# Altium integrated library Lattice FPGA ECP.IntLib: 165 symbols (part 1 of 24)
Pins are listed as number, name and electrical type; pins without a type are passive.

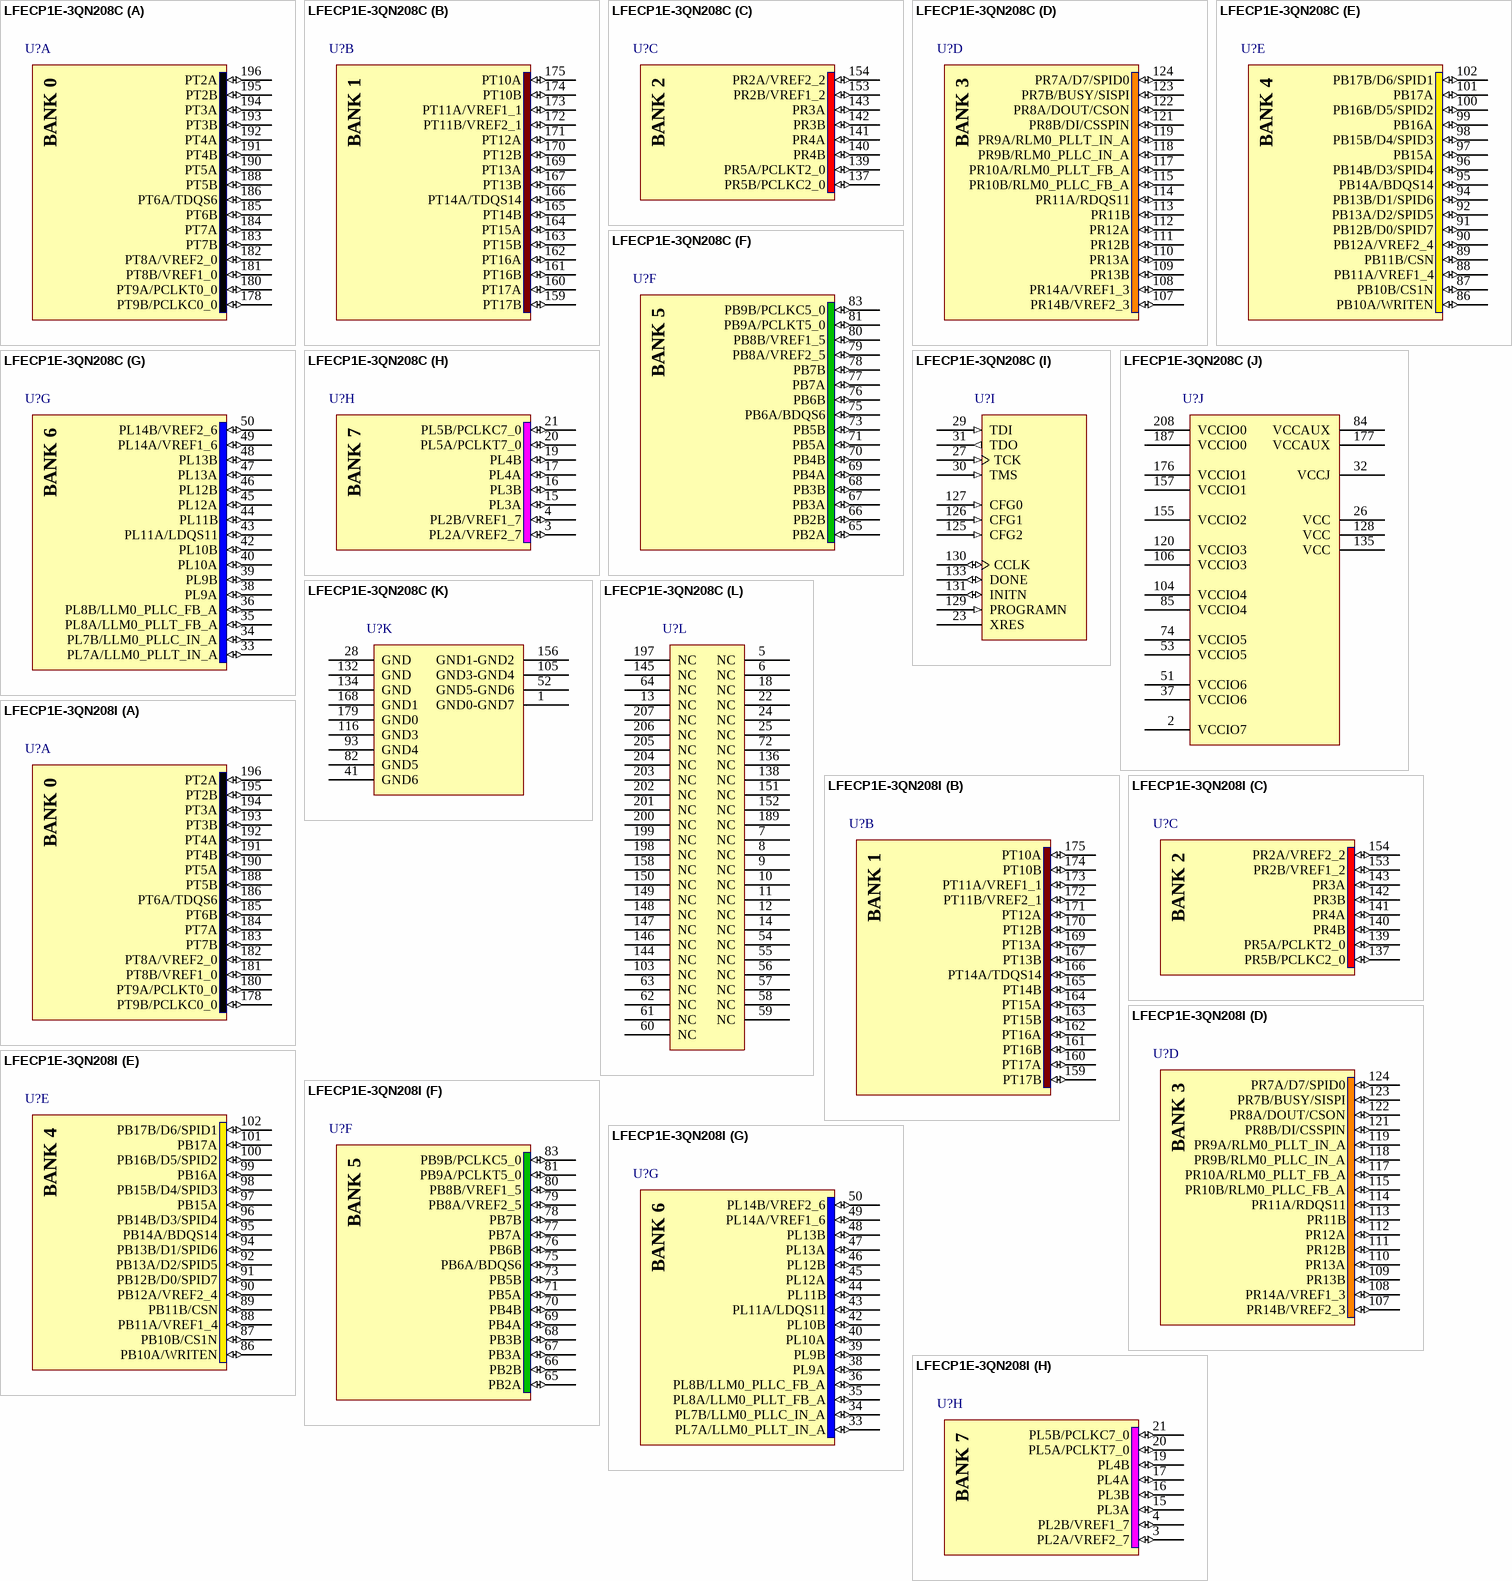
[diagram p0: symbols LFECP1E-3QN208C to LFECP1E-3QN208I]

## LFECP1E-3QN208C
designator U?
ECP 1.2V FPGA, 112 I/Os, 2 PLLs, 1.5K LUTs, 208-Pin PQFP, Pb-Free, Speed Grade 3, Commercial Temperature Grade; Note: Pins 1, 52, 105 and 156 are double bonded.; ComponentAvailability: Not Available
footprint PQFP208_N (Shrink QFP, 208-Leads, Body 28x28mm, Pitch 0.5mm, IPC Medium Density)
footprint PQFP208_L (Shrink QFP, 208-Leads, Body 28x28mm, Pitch 0.5mm, IPC High Density)
footprint PQFP208_M (Shrink QFP, 208-Leads, Body 28x28mm, Pitch 0.5mm, IPC Low Density)
3D model ECP1E-PQFP-208 (208-Pin Plastic Quad Flat Pack (PQFP208))
part A pins: 178 PT9B/PCLKC0_0 (io), 180 PT9A/PCLKT0_0 (io), 181 PT8B/VREF1_0 (io), 182 PT8A/VREF2_0 (io), 183 PT7B (io), 184 PT7A (io), 185 PT6B (io), 186 PT6A/TDQS6 (io), 188 PT5B (io), 190 PT5A (io), 191 PT4B (io), 192 PT4A (io), 193 PT3B (io), 194 PT3A (io), 195 PT2B (io), 196 PT2A (io)
part B pins: 159 PT17B (io), 160 PT17A (io), 161 PT16B (io), 162 PT16A (io), 163 PT15B (io), 164 PT15A (io), 165 PT14B (io), 166 PT14A/TDQS14 (io), 167 PT13B (io), 169 PT13A (io), 170 PT12B (io), 171 PT12A (io), 172 PT11B/VREF2_1 (io), 173 PT11A/VREF1_1 (io), 174 PT10B (io), 175 PT10A (io)
part C pins: 137 PR5B/PCLKC2_0 (io), 139 PR5A/PCLKT2_0 (io), 140 PR4B (io), 141 PR4A (io), 142 PR3B (io), 143 PR3A (io), 153 PR2B/VREF1_2 (io), 154 PR2A/VREF2_2 (io)
part D pins: 107 PR14B/VREF2_3 (io), 108 PR14A/VREF1_3 (io), 109 PR13B (io), 110 PR13A (io), 111 PR12B (io), 112 PR12A (io), 113 PR11B (io), 114 PR11A/RDQS11 (io), 115 PR10B/RLM0_PLLC_FB_A (io), 117 PR10A/RLM0_PLLT_FB_A (io), 118 PR9B/RLM0_PLLC_IN_A (io), 119 PR9A/RLM0_PLLT_IN_A (io), 121 PR8B/DI/CSSPIN (io), 122 PR8A/DOUT/CSON (io), 123 PR7B/BUSY/SISPI (io), 124 PR7A/D7/SPID0 (io)
part E pins: 86 PB10A/WRITEN (io), 87 PB10B/CS1N (io), 88 PB11A/VREF1_4 (io), 89 PB11B/CSN (io), 90 PB12A/VREF2_4 (io), 91 PB12B/D0/SPID7 (io), 92 PB13A/D2/SPID5 (io), 94 PB13B/D1/SPID6 (io), 95 PB14A/BDQS14 (io), 96 PB14B/D3/SPID4 (io), 97 PB15A (io), 98 PB15B/D4/SPID3 (io), 99 PB16A (io), 100 PB16B/D5/SPID2 (io), 101 PB17A (io), 102 PB17B/D6/SPID1 (io)
part F pins: 65 PB2A (io), 66 PB2B (io), 67 PB3A (io), 68 PB3B (io), 69 PB4A (io), 70 PB4B (io), 71 PB5A (io), 73 PB5B (io), 75 PB6A/BDQS6 (io), 76 PB6B (io), 77 PB7A (io), 78 PB7B (io), 79 PB8A/VREF2_5 (io), 80 PB8B/VREF1_5 (io), 81 PB9A/PCLKT5_0 (io), 83 PB9B/PCLKC5_0 (io)
part G pins: 33 PL7A/LLM0_PLLT_IN_A (io), 34 PL7B/LLM0_PLLC_IN_A (io), 35 PL8A/LLM0_PLLT_FB_A (io), 36 PL8B/LLM0_PLLC_FB_A (io), 38 PL9A (io), 39 PL9B (io), 40 PL10A (io), 42 PL10B (io), 43 PL11A/LDQS11 (io), 44 PL11B (io), 45 PL12A (io), 46 PL12B (io), 47 PL13A (io), 48 PL13B (io), 49 PL14A/VREF1_6 (io), 50 PL14B/VREF2_6 (io)
part H pins: 3 PL2A/VREF2_7 (io), 4 PL2B/VREF1_7 (io), 15 PL3A (io), 16 PL3B (io), 17 PL4A (io), 19 PL4B (io), 20 PL5A/PCLKT7_0 (io), 21 PL5B/PCLKC7_0 (io)
part I pins: 23 XRES, 27 TCK (in), 29 TDI (in), 30 TMS (in), 31 TDO (out), 125 CFG2 (in), 126 CFG1 (in), 127 CFG0 (in), 129 PROGRAMN (in), 130 CCLK (io), 131 INITN (io), 133 DONE (io)
part J pins: 2 VCCIO7 (power), 26 VCC (power), 32 VCCJ (power), 37 VCCIO6 (power), 51 VCCIO6 (power), 53 VCCIO5 (power), 74 VCCIO5 (power), 84 VCCAUX (power), 85 VCCIO4 (power), 104 VCCIO4 (power), 106 VCCIO3 (power), 120 VCCIO3 (power), 128 VCC (power), 135 VCC (power), 155 VCCIO2 (power), 157 VCCIO1 (power), 176 VCCIO1 (power), 177 VCCAUX (power), 187 VCCIO0 (power), 208 VCCIO0 (power)
part K pins: 1 GND0-GND7 (power), 28 GND (power), 41 GND6 (power), 52 GND5-GND6 (power), 82 GND5 (power), 93 GND4 (power), 105 GND3-GND4 (power), 116 GND3 (power), 132 GND (power), 134 GND (power), 156 GND1-GND2 (power), 168 GND1 (power), 179 GND0 (power)
part L pins: 5 NC, 6 NC, 7 NC, 8 NC, 9 NC, 10 NC, 11 NC, 12 NC, 13 NC, 14 NC, 18 NC, 22 NC, 24 NC, 25 NC, 54 NC, 55 NC, 56 NC, 57 NC, 58 NC, 59 NC, 60 NC, 61 NC, 62 NC, 63 NC, 64 NC, 72 NC, 103 NC, 136 NC, 138 NC, 144 NC, 145 NC, 146 NC, 147 NC, 148 NC, 149 NC, 150 NC, 151 NC, 152 NC, 158 NC, 189 NC, 197 NC, 198 NC, 199 NC, 200 NC, 201 NC, 202 NC, 203 NC, 204 NC, 205 NC, 206 NC, 207 NC

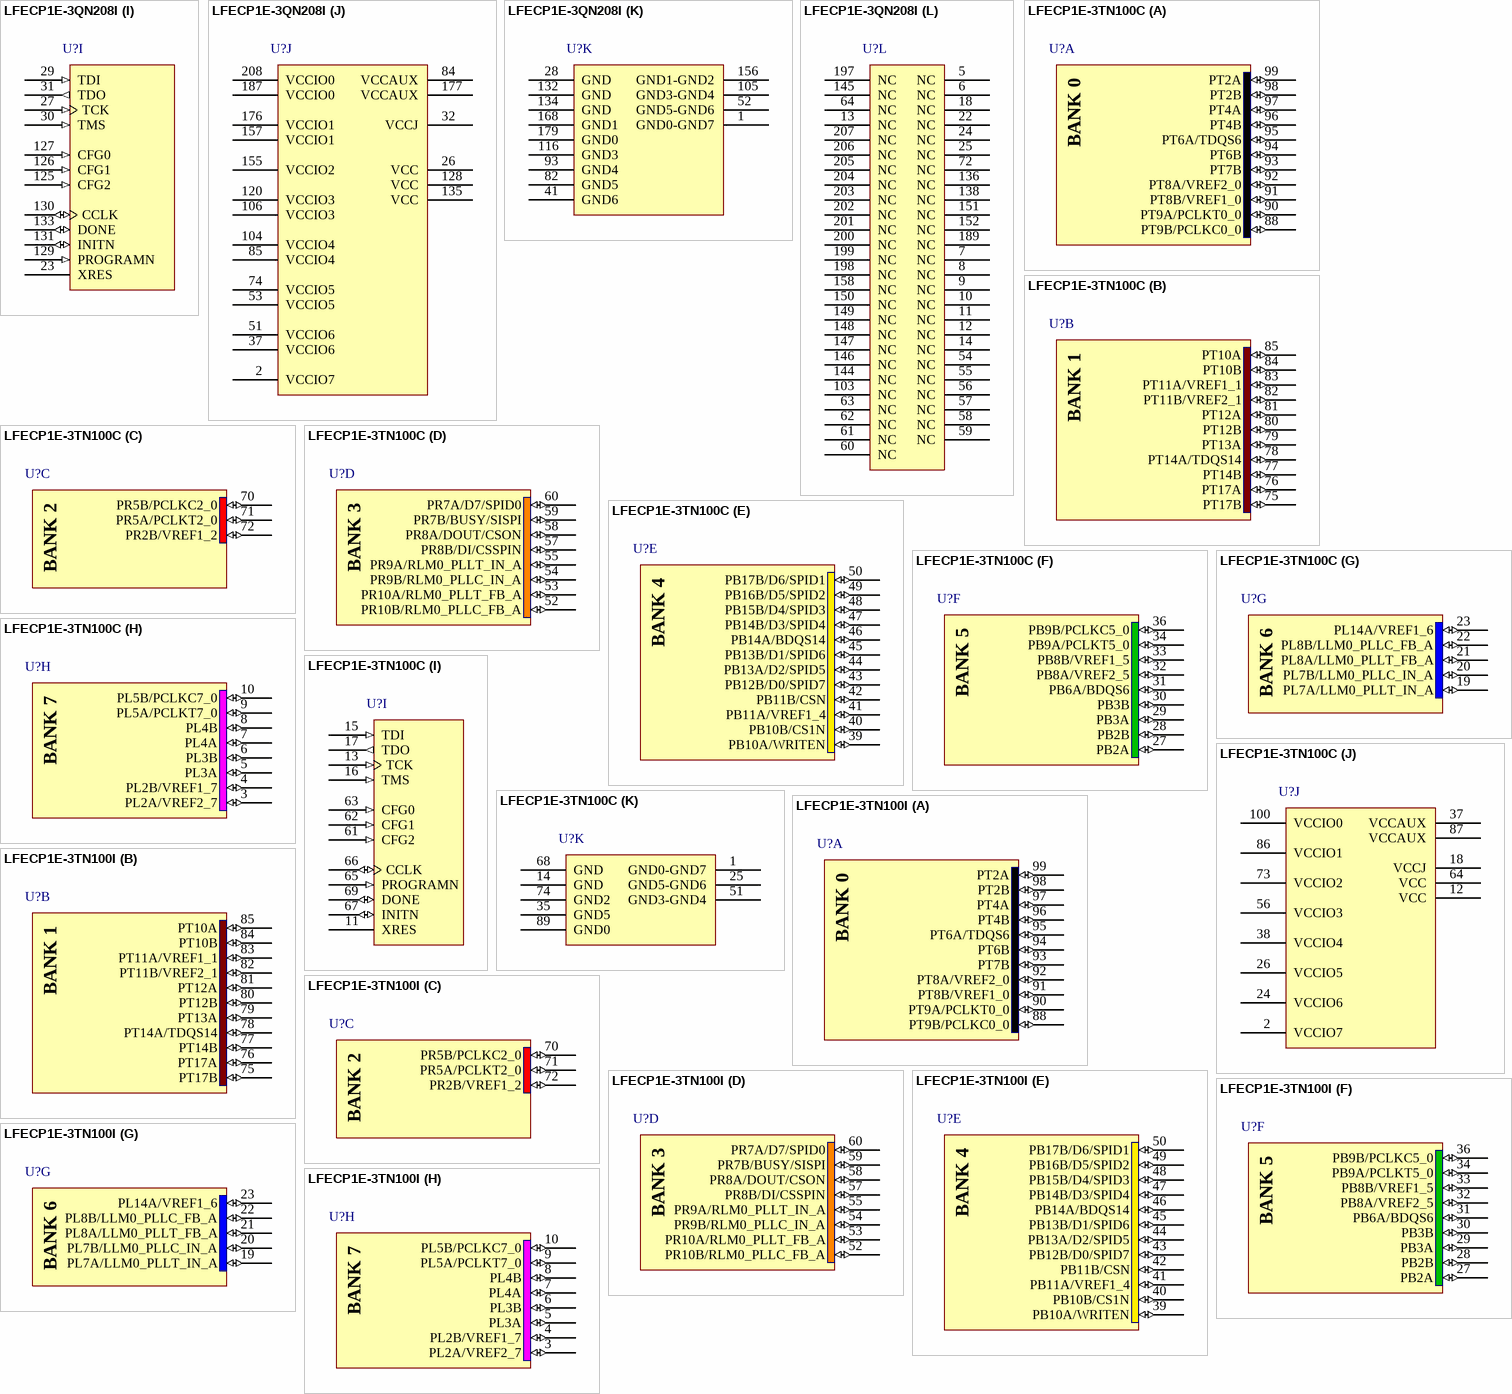
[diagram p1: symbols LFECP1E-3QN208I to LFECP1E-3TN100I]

## LFECP1E-3QN208I
designator U?
ECP 1.2V FPGA, 112 I/Os, 2 PLLs, 1.5K LUTs, 208-Pin PQFP, Pb-Free, Speed Grade 3, Industrial Temperature Grade; Note: Pins 1, 52, 105 and 156 are double bonded.; ComponentAvailability: Not Available
footprint PQFP208_N (Shrink QFP, 208-Leads, Body 28x28mm, Pitch 0.5mm, IPC Medium Density)
footprint PQFP208_L (Shrink QFP, 208-Leads, Body 28x28mm, Pitch 0.5mm, IPC High Density)
footprint PQFP208_M (Shrink QFP, 208-Leads, Body 28x28mm, Pitch 0.5mm, IPC Low Density)
3D model ECP1E-PQFP-208 (208-Pin Plastic Quad Flat Pack (PQFP208))
part A pins: 178 PT9B/PCLKC0_0 (io), 180 PT9A/PCLKT0_0 (io), 181 PT8B/VREF1_0 (io), 182 PT8A/VREF2_0 (io), 183 PT7B (io), 184 PT7A (io), 185 PT6B (io), 186 PT6A/TDQS6 (io), 188 PT5B (io), 190 PT5A (io), 191 PT4B (io), 192 PT4A (io), 193 PT3B (io), 194 PT3A (io), 195 PT2B (io), 196 PT2A (io)
part B pins: 159 PT17B (io), 160 PT17A (io), 161 PT16B (io), 162 PT16A (io), 163 PT15B (io), 164 PT15A (io), 165 PT14B (io), 166 PT14A/TDQS14 (io), 167 PT13B (io), 169 PT13A (io), 170 PT12B (io), 171 PT12A (io), 172 PT11B/VREF2_1 (io), 173 PT11A/VREF1_1 (io), 174 PT10B (io), 175 PT10A (io)
part C pins: 137 PR5B/PCLKC2_0 (io), 139 PR5A/PCLKT2_0 (io), 140 PR4B (io), 141 PR4A (io), 142 PR3B (io), 143 PR3A (io), 153 PR2B/VREF1_2 (io), 154 PR2A/VREF2_2 (io)
part D pins: 107 PR14B/VREF2_3 (io), 108 PR14A/VREF1_3 (io), 109 PR13B (io), 110 PR13A (io), 111 PR12B (io), 112 PR12A (io), 113 PR11B (io), 114 PR11A/RDQS11 (io), 115 PR10B/RLM0_PLLC_FB_A (io), 117 PR10A/RLM0_PLLT_FB_A (io), 118 PR9B/RLM0_PLLC_IN_A (io), 119 PR9A/RLM0_PLLT_IN_A (io), 121 PR8B/DI/CSSPIN (io), 122 PR8A/DOUT/CSON (io), 123 PR7B/BUSY/SISPI (io), 124 PR7A/D7/SPID0 (io)
part E pins: 86 PB10A/WRITEN (io), 87 PB10B/CS1N (io), 88 PB11A/VREF1_4 (io), 89 PB11B/CSN (io), 90 PB12A/VREF2_4 (io), 91 PB12B/D0/SPID7 (io), 92 PB13A/D2/SPID5 (io), 94 PB13B/D1/SPID6 (io), 95 PB14A/BDQS14 (io), 96 PB14B/D3/SPID4 (io), 97 PB15A (io), 98 PB15B/D4/SPID3 (io), 99 PB16A (io), 100 PB16B/D5/SPID2 (io), 101 PB17A (io), 102 PB17B/D6/SPID1 (io)
part F pins: 65 PB2A (io), 66 PB2B (io), 67 PB3A (io), 68 PB3B (io), 69 PB4A (io), 70 PB4B (io), 71 PB5A (io), 73 PB5B (io), 75 PB6A/BDQS6 (io), 76 PB6B (io), 77 PB7A (io), 78 PB7B (io), 79 PB8A/VREF2_5 (io), 80 PB8B/VREF1_5 (io), 81 PB9A/PCLKT5_0 (io), 83 PB9B/PCLKC5_0 (io)
part G pins: 33 PL7A/LLM0_PLLT_IN_A (io), 34 PL7B/LLM0_PLLC_IN_A (io), 35 PL8A/LLM0_PLLT_FB_A (io), 36 PL8B/LLM0_PLLC_FB_A (io), 38 PL9A (io), 39 PL9B (io), 40 PL10A (io), 42 PL10B (io), 43 PL11A/LDQS11 (io), 44 PL11B (io), 45 PL12A (io), 46 PL12B (io), 47 PL13A (io), 48 PL13B (io), 49 PL14A/VREF1_6 (io), 50 PL14B/VREF2_6 (io)
part H pins: 3 PL2A/VREF2_7 (io), 4 PL2B/VREF1_7 (io), 15 PL3A (io), 16 PL3B (io), 17 PL4A (io), 19 PL4B (io), 20 PL5A/PCLKT7_0 (io), 21 PL5B/PCLKC7_0 (io)
part I pins: 23 XRES, 27 TCK (in), 29 TDI (in), 30 TMS (in), 31 TDO (out), 125 CFG2 (in), 126 CFG1 (in), 127 CFG0 (in), 129 PROGRAMN (in), 130 CCLK (io), 131 INITN (io), 133 DONE (io)
part J pins: 2 VCCIO7 (power), 26 VCC (power), 32 VCCJ (power), 37 VCCIO6 (power), 51 VCCIO6 (power), 53 VCCIO5 (power), 74 VCCIO5 (power), 84 VCCAUX (power), 85 VCCIO4 (power), 104 VCCIO4 (power), 106 VCCIO3 (power), 120 VCCIO3 (power), 128 VCC (power), 135 VCC (power), 155 VCCIO2 (power), 157 VCCIO1 (power), 176 VCCIO1 (power), 177 VCCAUX (power), 187 VCCIO0 (power), 208 VCCIO0 (power)
part K pins: 1 GND0-GND7 (power), 28 GND (power), 41 GND6 (power), 52 GND5-GND6 (power), 82 GND5 (power), 93 GND4 (power), 105 GND3-GND4 (power), 116 GND3 (power), 132 GND (power), 134 GND (power), 156 GND1-GND2 (power), 168 GND1 (power), 179 GND0 (power)
part L pins: 5 NC, 6 NC, 7 NC, 8 NC, 9 NC, 10 NC, 11 NC, 12 NC, 13 NC, 14 NC, 18 NC, 22 NC, 24 NC, 25 NC, 54 NC, 55 NC, 56 NC, 57 NC, 58 NC, 59 NC, 60 NC, 61 NC, 62 NC, 63 NC, 64 NC, 72 NC, 103 NC, 136 NC, 138 NC, 144 NC, 145 NC, 146 NC, 147 NC, 148 NC, 149 NC, 150 NC, 151 NC, 152 NC, 158 NC, 189 NC, 197 NC, 198 NC, 199 NC, 200 NC, 201 NC, 202 NC, 203 NC, 204 NC, 205 NC, 206 NC, 207 NC

## LFECP1E-3TN100C
designator U?
ECP 1.2V FPGA, 67 I/Os, 2 PLLs, 1.5K LUTs, 100-Pin TQFP, Pb-Free, Speed Grade 3, Commercial Temperature Grade; Note: Pins 1, 25 and 51 are double bonded.; ComponentAvailability: Not Available
footprint TQFP100_N (Thin QFP, 100-Leads, Body 14x14mm, Pitch 0.5mm, IPC Medium Density)
footprint TQFP100_L (Thin QFP, 100-Leads, Body 14x14mm, Pitch 0.5mm, IPC High Density)
footprint TQFP100_M (Thin QFP, 100-Leads, Body 14x14mm, Pitch 0.5mm, IPC Low Density)
3D model ECP1E-TQFP-100 (100-Pin Thin Quad Flat Pack (TQFP100))
part A pins: 88 PT9B/PCLKC0_0 (io), 90 PT9A/PCLKT0_0 (io), 91 PT8B/VREF1_0 (io), 92 PT8A/VREF2_0 (io), 93 PT7B (io), 94 PT6B (io), 95 PT6A/TDQS6 (io), 96 PT4B (io), 97 PT4A (io), 98 PT2B (io), 99 PT2A (io)
part B pins: 75 PT17B (io), 76 PT17A (io), 77 PT14B (io), 78 PT14A/TDQS14 (io), 79 PT13A (io), 80 PT12B (io), 81 PT12A (io), 82 PT11B/VREF2_1 (io), 83 PT11A/VREF1_1 (io), 84 PT10B (io), 85 PT10A (io)
part C pins: 70 PR5B/PCLKC2_0 (io), 71 PR5A/PCLKT2_0 (io), 72 PR2B/VREF1_2 (io)
part D pins: 52 PR10B/RLM0_PLLC_FB_A (io), 53 PR10A/RLM0_PLLT_FB_A (io), 54 PR9B/RLM0_PLLC_IN_A (io), 55 PR9A/RLM0_PLLT_IN_A (io), 57 PR8B/DI/CSSPIN (io), 58 PR8A/DOUT/CSON (io), 59 PR7B/BUSY/SISPI (io), 60 PR7A/D7/SPID0 (io)
part E pins: 39 PB10A/WRITEN (io), 40 PB10B/CS1N (io), 41 PB11A/VREF1_4 (io), 42 PB11B/CSN (io), 43 PB12B/D0/SPID7 (io), 44 PB13A/D2/SPID5 (io), 45 PB13B/D1/SPID6 (io), 46 PB14A/BDQS14 (io), 47 PB14B/D3/SPID4 (io), 48 PB15B/D4/SPID3 (io), 49 PB16B/D5/SPID2 (io), 50 PB17B/D6/SPID1 (io)
part F pins: 27 PB2A (io), 28 PB2B (io), 29 PB3A (io), 30 PB3B (io), 31 PB6A/BDQS6 (io), 32 PB8A/VREF2_5 (io), 33 PB8B/VREF1_5 (io), 34 PB9A/PCLKT5_0 (io), 36 PB9B/PCLKC5_0 (io)
part G pins: 19 PL7A/LLM0_PLLT_IN_A (io), 20 PL7B/LLM0_PLLC_IN_A (io), 21 PL8A/LLM0_PLLT_FB_A (io), 22 PL8B/LLM0_PLLC_FB_A (io), 23 PL14A/VREF1_6 (io)
part H pins: 3 PL2A/VREF2_7 (io), 4 PL2B/VREF1_7 (io), 5 PL3A (io), 6 PL3B (io), 7 PL4A (io), 8 PL4B (io), 9 PL5A/PCLKT7_0 (io), 10 PL5B/PCLKC7_0 (io)
part I pins: 11 XRES, 13 TCK (in), 15 TDI (in), 16 TMS (in), 17 TDO (out), 61 CFG2 (in), 62 CFG1 (in), 63 CFG0 (in), 65 PROGRAMN (in), 66 CCLK (io), 67 INITN (io), 69 DONE (io)
part J pins: 2 VCCIO7 (power), 12 VCC (power), 18 VCCJ (power), 24 VCCIO6 (power), 26 VCCIO5 (power), 37 VCCAUX (power), 38 VCCIO4 (power), 56 VCCIO3 (power), 64 VCC (power), 73 VCCIO2 (power), 86 VCCIO1 (power), 87 VCCAUX (power), 100 VCCIO0 (power)
part K pins: 1 GND0-GND7 (power), 14 GND (power), 25 GND5-GND6 (power), 35 GND5 (power), 51 GND3-GND4 (power), 68 GND (power), 74 GND2 (power), 89 GND0 (power)

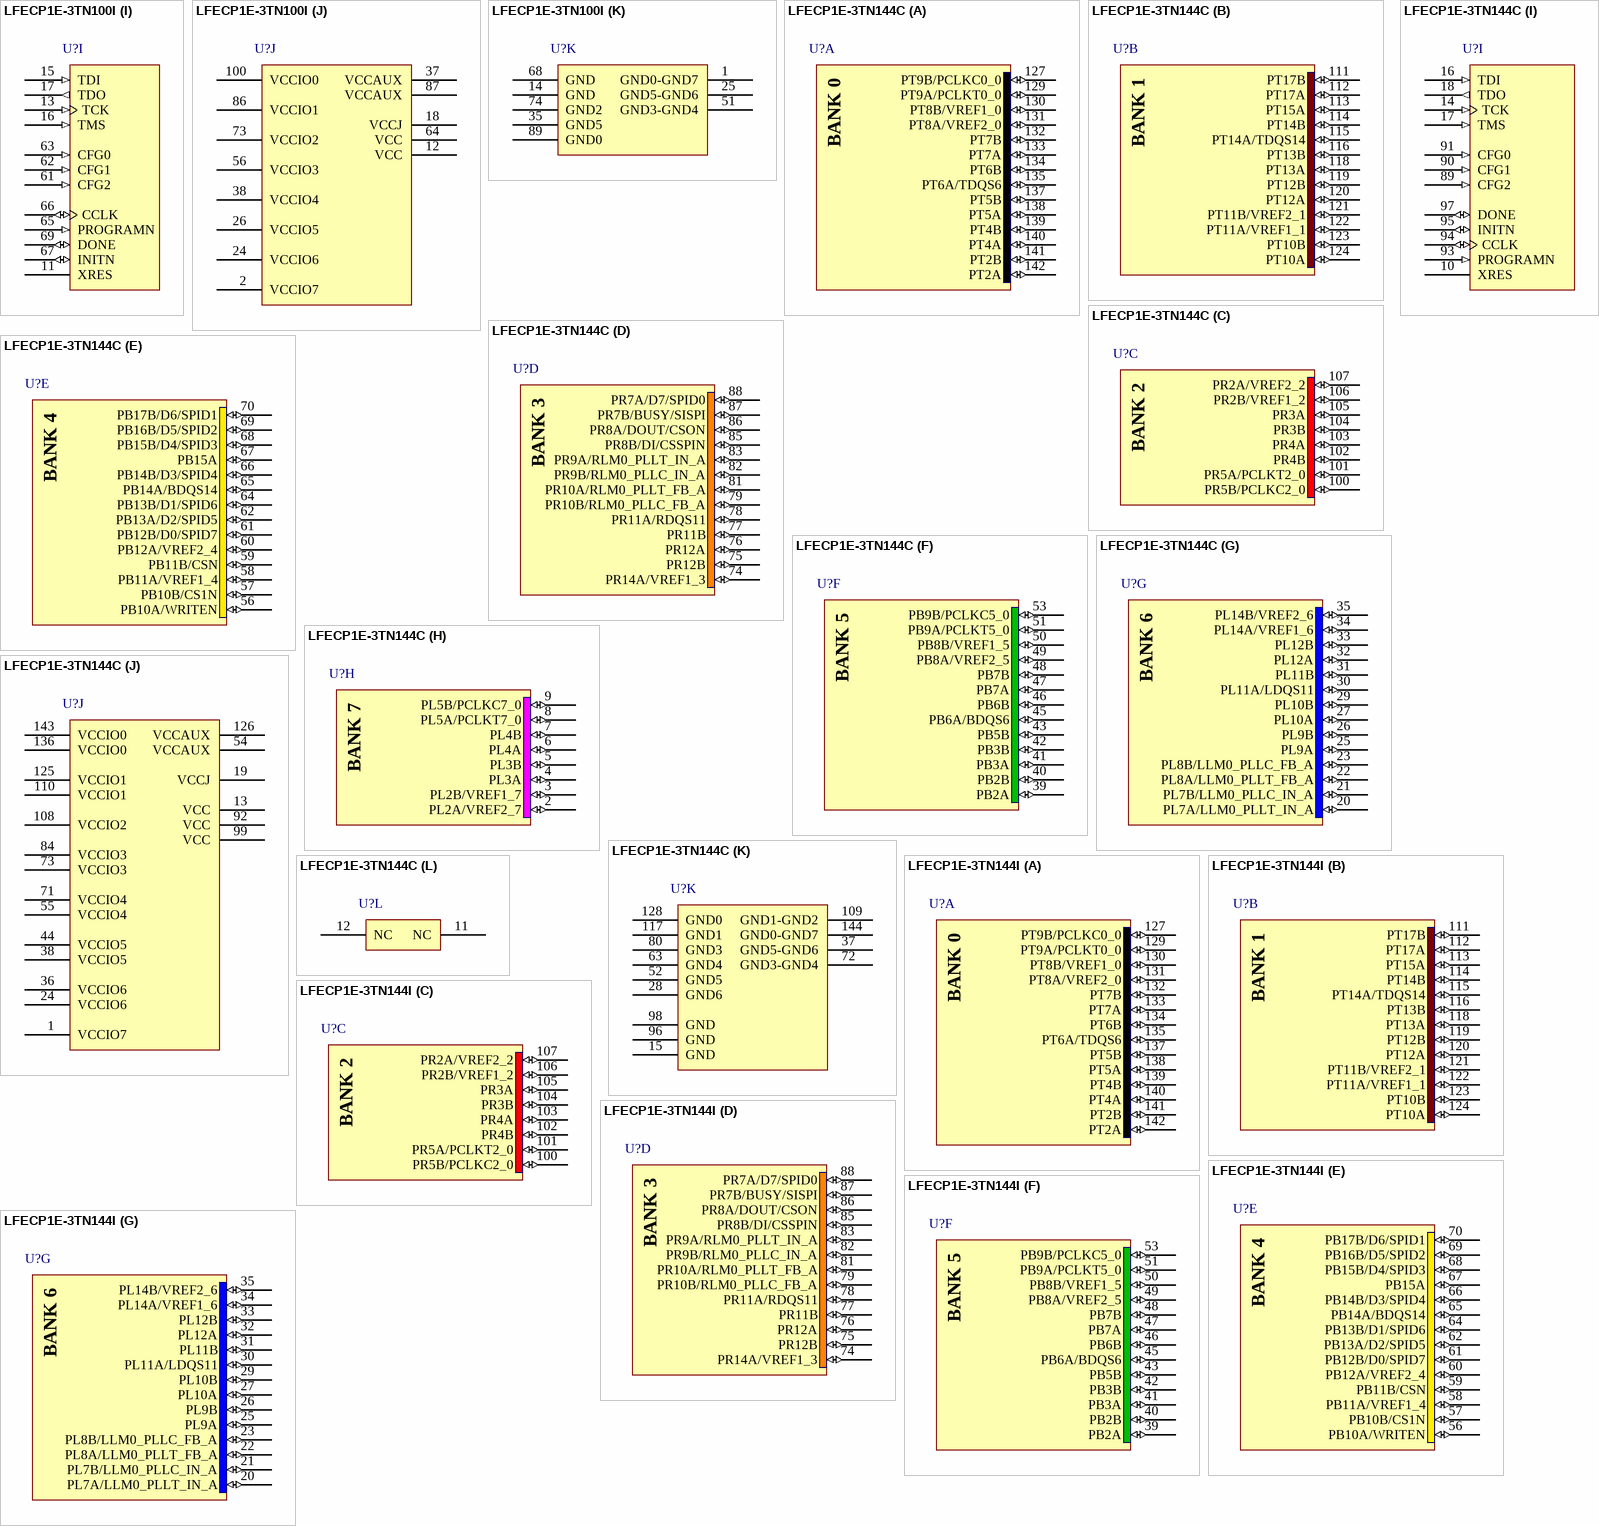
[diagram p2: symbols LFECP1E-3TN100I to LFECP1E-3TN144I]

## LFECP1E-3TN100I
designator U?
ECP 1.2V FPGA, 67 I/Os, 2 PLLs, 1.5K LUTs, 100-Pin TQFP, Pb-Free, Speed Grade 3, Industrial Temperature Grade; Note: Pins 1, 25 and 51 are double bonded.; ComponentAvailability: Not Available
footprint TQFP100_N (Thin QFP, 100-Leads, Body 14x14mm, Pitch 0.5mm, IPC Medium Density)
footprint TQFP100_L (Thin QFP, 100-Leads, Body 14x14mm, Pitch 0.5mm, IPC High Density)
footprint TQFP100_M (Thin QFP, 100-Leads, Body 14x14mm, Pitch 0.5mm, IPC Low Density)
3D model ECP1E-TQFP-100 (100-Pin Thin Quad Flat Pack (TQFP100))
part A pins: 88 PT9B/PCLKC0_0 (io), 90 PT9A/PCLKT0_0 (io), 91 PT8B/VREF1_0 (io), 92 PT8A/VREF2_0 (io), 93 PT7B (io), 94 PT6B (io), 95 PT6A/TDQS6 (io), 96 PT4B (io), 97 PT4A (io), 98 PT2B (io), 99 PT2A (io)
part B pins: 75 PT17B (io), 76 PT17A (io), 77 PT14B (io), 78 PT14A/TDQS14 (io), 79 PT13A (io), 80 PT12B (io), 81 PT12A (io), 82 PT11B/VREF2_1 (io), 83 PT11A/VREF1_1 (io), 84 PT10B (io), 85 PT10A (io)
part C pins: 70 PR5B/PCLKC2_0 (io), 71 PR5A/PCLKT2_0 (io), 72 PR2B/VREF1_2 (io)
part D pins: 52 PR10B/RLM0_PLLC_FB_A (io), 53 PR10A/RLM0_PLLT_FB_A (io), 54 PR9B/RLM0_PLLC_IN_A (io), 55 PR9A/RLM0_PLLT_IN_A (io), 57 PR8B/DI/CSSPIN (io), 58 PR8A/DOUT/CSON (io), 59 PR7B/BUSY/SISPI (io), 60 PR7A/D7/SPID0 (io)
part E pins: 39 PB10A/WRITEN (io), 40 PB10B/CS1N (io), 41 PB11A/VREF1_4 (io), 42 PB11B/CSN (io), 43 PB12B/D0/SPID7 (io), 44 PB13A/D2/SPID5 (io), 45 PB13B/D1/SPID6 (io), 46 PB14A/BDQS14 (io), 47 PB14B/D3/SPID4 (io), 48 PB15B/D4/SPID3 (io), 49 PB16B/D5/SPID2 (io), 50 PB17B/D6/SPID1 (io)
part F pins: 27 PB2A (io), 28 PB2B (io), 29 PB3A (io), 30 PB3B (io), 31 PB6A/BDQS6 (io), 32 PB8A/VREF2_5 (io), 33 PB8B/VREF1_5 (io), 34 PB9A/PCLKT5_0 (io), 36 PB9B/PCLKC5_0 (io)
part G pins: 19 PL7A/LLM0_PLLT_IN_A (io), 20 PL7B/LLM0_PLLC_IN_A (io), 21 PL8A/LLM0_PLLT_FB_A (io), 22 PL8B/LLM0_PLLC_FB_A (io), 23 PL14A/VREF1_6 (io)
part H pins: 3 PL2A/VREF2_7 (io), 4 PL2B/VREF1_7 (io), 5 PL3A (io), 6 PL3B (io), 7 PL4A (io), 8 PL4B (io), 9 PL5A/PCLKT7_0 (io), 10 PL5B/PCLKC7_0 (io)
part I pins: 11 XRES, 13 TCK (in), 15 TDI (in), 16 TMS (in), 17 TDO (out), 61 CFG2 (in), 62 CFG1 (in), 63 CFG0 (in), 65 PROGRAMN (in), 66 CCLK (io), 67 INITN (io), 69 DONE (io)
part J pins: 2 VCCIO7 (power), 12 VCC (power), 18 VCCJ (power), 24 VCCIO6 (power), 26 VCCIO5 (power), 37 VCCAUX (power), 38 VCCIO4 (power), 56 VCCIO3 (power), 64 VCC (power), 73 VCCIO2 (power), 86 VCCIO1 (power), 87 VCCAUX (power), 100 VCCIO0 (power)
part K pins: 1 GND0-GND7 (power), 14 GND (power), 25 GND5-GND6 (power), 35 GND5 (power), 51 GND3-GND4 (power), 68 GND (power), 74 GND2 (power), 89 GND0 (power)

## LFECP1E-3TN144C
designator U?
ECP 1.2V FPGA, 97 I/Os, 2 PLLs, 1.5K LUTs, 144-Pin TQFP, Pb-Free, Speed Grade 3, Commercial Temperature Grade; Note: Pins 37, 72, 109 and 144 are double bonded.; ComponentAvailability: Not Available
footprint TQFP144_N (Thin QFP, 144-Leads, Body 20x20mm, Pitch 0.5mm, IPC Medium Density)
footprint TQFP144_L (Thin QFP, 144-Leads, Body 20x20mm, Pitch 0.5mm, IPC High Density)
footprint TQFP144_M (Thin QFP, 144-Leads, Body 20x20mm, Pitch 0.5mm, IPC Low Density)
3D model ECP1E-TQFP-144 (144-Pin Thin Quad Flat Pack (TQFP144))
part A pins: 127 PT9B/PCLKC0_0 (io), 129 PT9A/PCLKT0_0 (io), 130 PT8B/VREF1_0 (io), 131 PT8A/VREF2_0 (io), 132 PT7B (io), 133 PT7A (io), 134 PT6B (io), 135 PT6A/TDQS6 (io), 137 PT5B (io), 138 PT5A (io), 139 PT4B (io), 140 PT4A (io), 141 PT2B (io), 142 PT2A (io)
part B pins: 111 PT17B (io), 112 PT17A (io), 113 PT15A (io), 114 PT14B (io), 115 PT14A/TDQS14 (io), 116 PT13B (io), 118 PT13A (io), 119 PT12B (io), 120 PT12A (io), 121 PT11B/VREF2_1 (io), 122 PT11A/VREF1_1 (io), 123 PT10B (io), 124 PT10A (io)
part C pins: 100 PR5B/PCLKC2_0 (io), 101 PR5A/PCLKT2_0 (io), 102 PR4B (io), 103 PR4A (io), 104 PR3B (io), 105 PR3A (io), 106 PR2B/VREF1_2 (io), 107 PR2A/VREF2_2 (io)
part D pins: 74 PR14A/VREF1_3 (io), 75 PR12B (io), 76 PR12A (io), 77 PR11B (io), 78 PR11A/RDQS11 (io), 79 PR10B/RLM0_PLLC_FB_A (io), 81 PR10A/RLM0_PLLT_FB_A (io), 82 PR9B/RLM0_PLLC_IN_A (io), 83 PR9A/RLM0_PLLT_IN_A (io), 85 PR8B/DI/CSSPIN (io), 86 PR8A/DOUT/CSON (io), 87 PR7B/BUSY/SISPI (io), 88 PR7A/D7/SPID0 (io)
part E pins: 56 PB10A/WRITEN (io), 57 PB10B/CS1N (io), 58 PB11A/VREF1_4 (io), 59 PB11B/CSN (io), 60 PB12A/VREF2_4 (io), 61 PB12B/D0/SPID7 (io), 62 PB13A/D2/SPID5 (io), 64 PB13B/D1/SPID6 (io), 65 PB14A/BDQS14 (io), 66 PB14B/D3/SPID4 (io), 67 PB15A (io), 68 PB15B/D4/SPID3 (io), 69 PB16B/D5/SPID2 (io), 70 PB17B/D6/SPID1 (io)
part F pins: 39 PB2A (io), 40 PB2B (io), 41 PB3A (io), 42 PB3B (io), 43 PB5B (io), 45 PB6A/BDQS6 (io), 46 PB6B (io), 47 PB7A (io), 48 PB7B (io), 49 PB8A/VREF2_5 (io), 50 PB8B/VREF1_5 (io), 51 PB9A/PCLKT5_0 (io), 53 PB9B/PCLKC5_0 (io)
part G pins: 20 PL7A/LLM0_PLLT_IN_A (io), 21 PL7B/LLM0_PLLC_IN_A (io), 22 PL8A/LLM0_PLLT_FB_A (io), 23 PL8B/LLM0_PLLC_FB_A (io), 25 PL9A (io), 26 PL9B (io), 27 PL10A (io), 29 PL10B (io), 30 PL11A/LDQS11 (io), 31 PL11B (io), 32 PL12A (io), 33 PL12B (io), 34 PL14A/VREF1_6 (io), 35 PL14B/VREF2_6 (io)
part H pins: 2 PL2A/VREF2_7 (io), 3 PL2B/VREF1_7 (io), 4 PL3A (io), 5 PL3B (io), 6 PL4A (io), 7 PL4B (io), 8 PL5A/PCLKT7_0 (io), 9 PL5B/PCLKC7_0 (io)
part I pins: 10 XRES, 14 TCK (in), 16 TDI (in), 17 TMS (in), 18 TDO (out), 89 CFG2 (in), 90 CFG1 (in), 91 CFG0 (in), 93 PROGRAMN (in), 94 CCLK (io), 95 INITN (io), 97 DONE (io)
part J pins: 1 VCCIO7 (power), 13 VCC (power), 19 VCCJ (power), 24 VCCIO6 (power), 36 VCCIO6 (power), 38 VCCIO5 (power), 44 VCCIO5 (power), 54 VCCAUX (power), 55 VCCIO4 (power), 71 VCCIO4 (power), 73 VCCIO3 (power), 84 VCCIO3 (power), 92 VCC (power), 99 VCC (power), 108 VCCIO2 (power), 110 VCCIO1 (power), 125 VCCIO1 (power), 126 VCCAUX (power), 136 VCCIO0 (power), 143 VCCIO0 (power)
part K pins: 15 GND (power), 28 GND6 (power), 37 GND5-GND6 (power), 52 GND5 (power), 63 GND4 (power), 72 GND3-GND4 (power), 80 GND3 (power), 96 GND (power), 98 GND (power), 109 GND1-GND2 (power), 117 GND1 (power), 128 GND0 (power), 144 GND0-GND7 (power)
part L pins: 11 NC, 12 NC

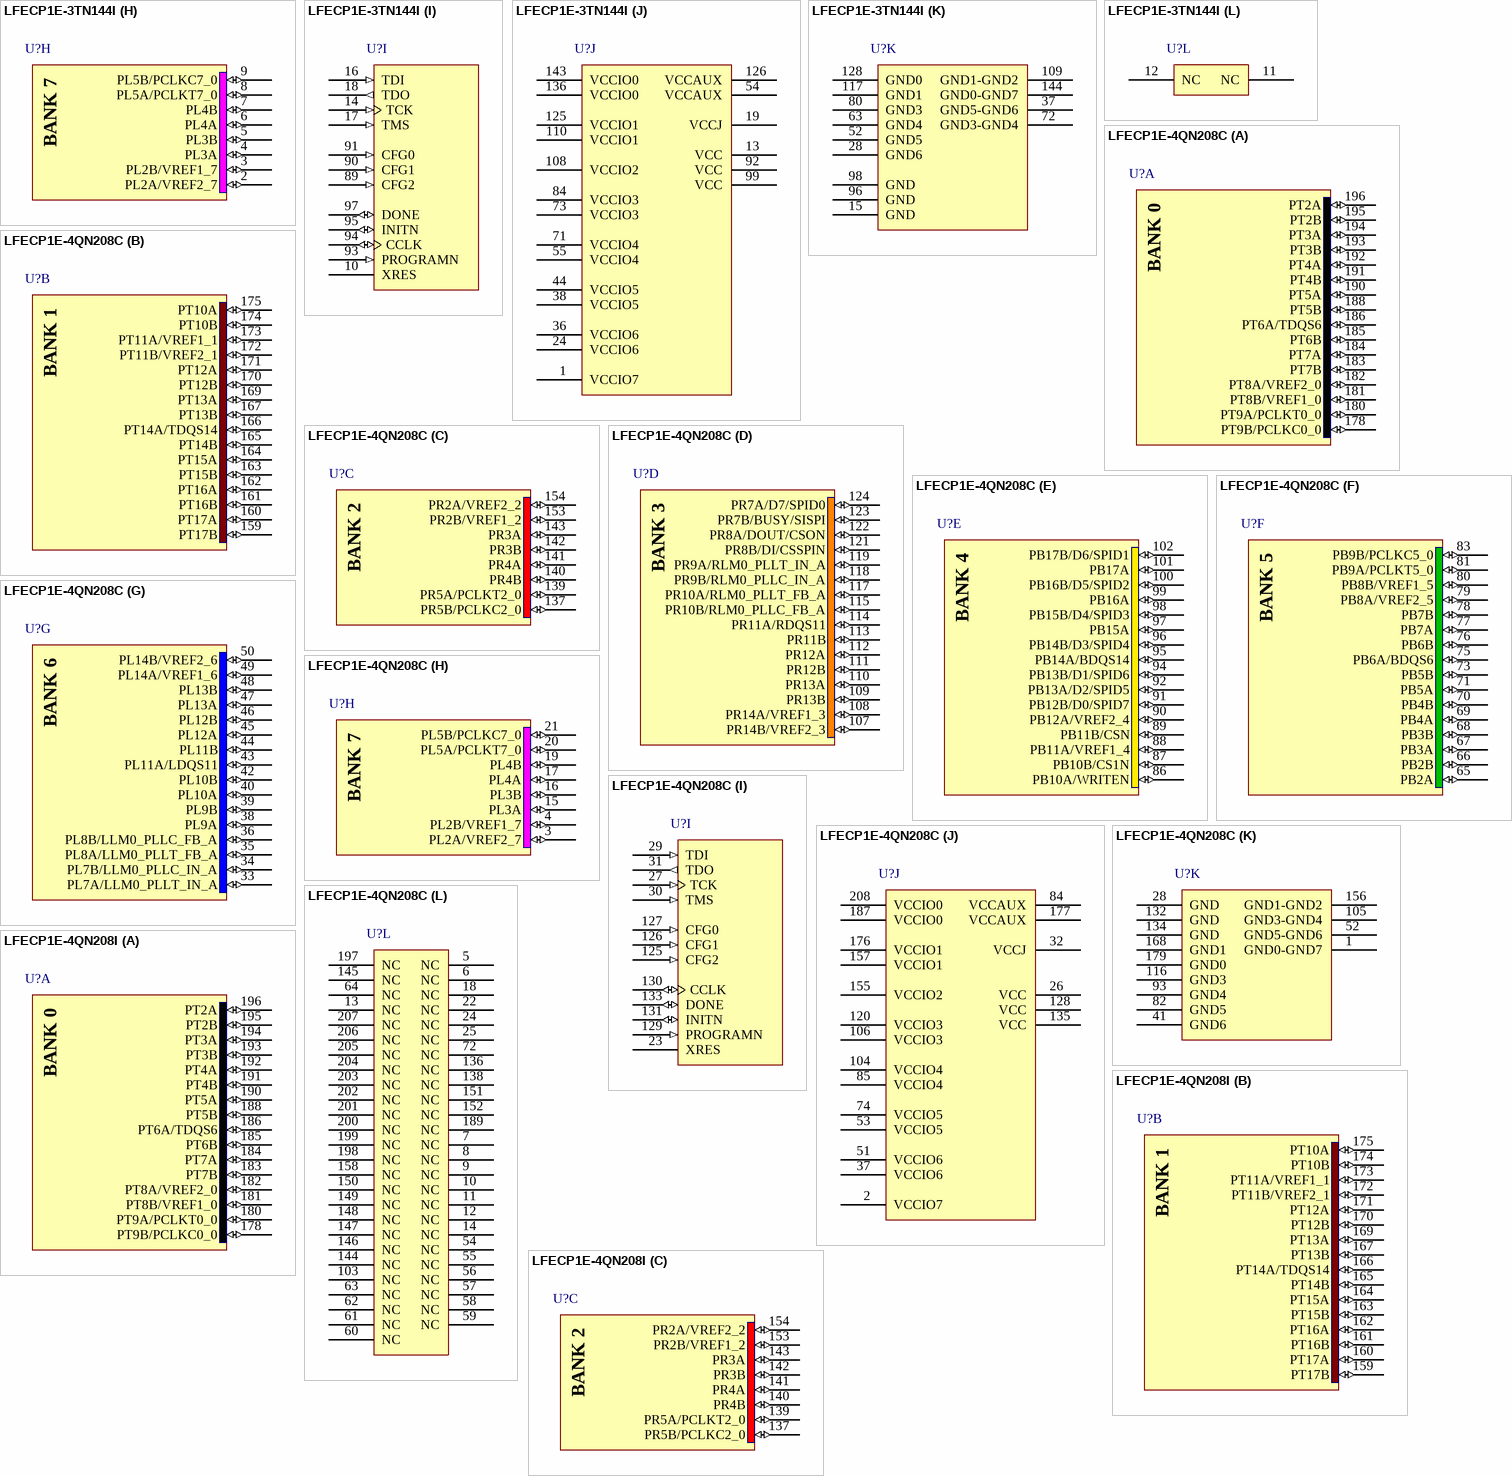
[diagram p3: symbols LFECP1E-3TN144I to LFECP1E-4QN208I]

## LFECP1E-3TN144I
designator U?
ECP 1.2V FPGA, 97 I/Os, 2 PLLs, 1.5K LUTs, 144-Pin TQFP, Pb-Free, Speed Grade 3, Industrial Temperature Grade; Note: Pins 37, 72, 109 and 144 are double bonded.; ComponentAvailability: Not Available
footprint TQFP144_N (Thin QFP, 144-Leads, Body 20x20mm, Pitch 0.5mm, IPC Medium Density)
footprint TQFP144_L (Thin QFP, 144-Leads, Body 20x20mm, Pitch 0.5mm, IPC High Density)
footprint TQFP144_M (Thin QFP, 144-Leads, Body 20x20mm, Pitch 0.5mm, IPC Low Density)
3D model ECP1E-TQFP-144 (144-Pin Thin Quad Flat Pack (TQFP144))
part A pins: 127 PT9B/PCLKC0_0 (io), 129 PT9A/PCLKT0_0 (io), 130 PT8B/VREF1_0 (io), 131 PT8A/VREF2_0 (io), 132 PT7B (io), 133 PT7A (io), 134 PT6B (io), 135 PT6A/TDQS6 (io), 137 PT5B (io), 138 PT5A (io), 139 PT4B (io), 140 PT4A (io), 141 PT2B (io), 142 PT2A (io)
part B pins: 111 PT17B (io), 112 PT17A (io), 113 PT15A (io), 114 PT14B (io), 115 PT14A/TDQS14 (io), 116 PT13B (io), 118 PT13A (io), 119 PT12B (io), 120 PT12A (io), 121 PT11B/VREF2_1 (io), 122 PT11A/VREF1_1 (io), 123 PT10B (io), 124 PT10A (io)
part C pins: 100 PR5B/PCLKC2_0 (io), 101 PR5A/PCLKT2_0 (io), 102 PR4B (io), 103 PR4A (io), 104 PR3B (io), 105 PR3A (io), 106 PR2B/VREF1_2 (io), 107 PR2A/VREF2_2 (io)
part D pins: 74 PR14A/VREF1_3 (io), 75 PR12B (io), 76 PR12A (io), 77 PR11B (io), 78 PR11A/RDQS11 (io), 79 PR10B/RLM0_PLLC_FB_A (io), 81 PR10A/RLM0_PLLT_FB_A (io), 82 PR9B/RLM0_PLLC_IN_A (io), 83 PR9A/RLM0_PLLT_IN_A (io), 85 PR8B/DI/CSSPIN (io), 86 PR8A/DOUT/CSON (io), 87 PR7B/BUSY/SISPI (io), 88 PR7A/D7/SPID0 (io)
part E pins: 56 PB10A/WRITEN (io), 57 PB10B/CS1N (io), 58 PB11A/VREF1_4 (io), 59 PB11B/CSN (io), 60 PB12A/VREF2_4 (io), 61 PB12B/D0/SPID7 (io), 62 PB13A/D2/SPID5 (io), 64 PB13B/D1/SPID6 (io), 65 PB14A/BDQS14 (io), 66 PB14B/D3/SPID4 (io), 67 PB15A (io), 68 PB15B/D4/SPID3 (io), 69 PB16B/D5/SPID2 (io), 70 PB17B/D6/SPID1 (io)
part F pins: 39 PB2A (io), 40 PB2B (io), 41 PB3A (io), 42 PB3B (io), 43 PB5B (io), 45 PB6A/BDQS6 (io), 46 PB6B (io), 47 PB7A (io), 48 PB7B (io), 49 PB8A/VREF2_5 (io), 50 PB8B/VREF1_5 (io), 51 PB9A/PCLKT5_0 (io), 53 PB9B/PCLKC5_0 (io)
part G pins: 20 PL7A/LLM0_PLLT_IN_A (io), 21 PL7B/LLM0_PLLC_IN_A (io), 22 PL8A/LLM0_PLLT_FB_A (io), 23 PL8B/LLM0_PLLC_FB_A (io), 25 PL9A (io), 26 PL9B (io), 27 PL10A (io), 29 PL10B (io), 30 PL11A/LDQS11 (io), 31 PL11B (io), 32 PL12A (io), 33 PL12B (io), 34 PL14A/VREF1_6 (io), 35 PL14B/VREF2_6 (io)
part H pins: 2 PL2A/VREF2_7 (io), 3 PL2B/VREF1_7 (io), 4 PL3A (io), 5 PL3B (io), 6 PL4A (io), 7 PL4B (io), 8 PL5A/PCLKT7_0 (io), 9 PL5B/PCLKC7_0 (io)
part I pins: 10 XRES, 14 TCK (in), 16 TDI (in), 17 TMS (in), 18 TDO (out), 89 CFG2 (in), 90 CFG1 (in), 91 CFG0 (in), 93 PROGRAMN (in), 94 CCLK (io), 95 INITN (io), 97 DONE (io)
part J pins: 1 VCCIO7 (power), 13 VCC (power), 19 VCCJ (power), 24 VCCIO6 (power), 36 VCCIO6 (power), 38 VCCIO5 (power), 44 VCCIO5 (power), 54 VCCAUX (power), 55 VCCIO4 (power), 71 VCCIO4 (power), 73 VCCIO3 (power), 84 VCCIO3 (power), 92 VCC (power), 99 VCC (power), 108 VCCIO2 (power), 110 VCCIO1 (power), 125 VCCIO1 (power), 126 VCCAUX (power), 136 VCCIO0 (power), 143 VCCIO0 (power)
part K pins: 15 GND (power), 28 GND6 (power), 37 GND5-GND6 (power), 52 GND5 (power), 63 GND4 (power), 72 GND3-GND4 (power), 80 GND3 (power), 96 GND (power), 98 GND (power), 109 GND1-GND2 (power), 117 GND1 (power), 128 GND0 (power), 144 GND0-GND7 (power)
part L pins: 11 NC, 12 NC

## LFECP1E-4QN208C
designator U?
ECP 1.2V FPGA, 112 I/Os, 2 PLLs, 1.5K LUTs, 208-Pin PQFP, Pb-Free, Speed Grade 4, Commercial Temperature Grade; Note: Pins 1, 52, 105 and 156 are double bonded.; ComponentAvailability: Not Available
footprint PQFP208_N (Shrink QFP, 208-Leads, Body 28x28mm, Pitch 0.5mm, IPC Medium Density)
footprint PQFP208_L (Shrink QFP, 208-Leads, Body 28x28mm, Pitch 0.5mm, IPC High Density)
footprint PQFP208_M (Shrink QFP, 208-Leads, Body 28x28mm, Pitch 0.5mm, IPC Low Density)
3D model ECP1E-PQFP-208 (208-Pin Plastic Quad Flat Pack (PQFP208))
part A pins: 178 PT9B/PCLKC0_0 (io), 180 PT9A/PCLKT0_0 (io), 181 PT8B/VREF1_0 (io), 182 PT8A/VREF2_0 (io), 183 PT7B (io), 184 PT7A (io), 185 PT6B (io), 186 PT6A/TDQS6 (io), 188 PT5B (io), 190 PT5A (io), 191 PT4B (io), 192 PT4A (io), 193 PT3B (io), 194 PT3A (io), 195 PT2B (io), 196 PT2A (io)
part B pins: 159 PT17B (io), 160 PT17A (io), 161 PT16B (io), 162 PT16A (io), 163 PT15B (io), 164 PT15A (io), 165 PT14B (io), 166 PT14A/TDQS14 (io), 167 PT13B (io), 169 PT13A (io), 170 PT12B (io), 171 PT12A (io), 172 PT11B/VREF2_1 (io), 173 PT11A/VREF1_1 (io), 174 PT10B (io), 175 PT10A (io)
part C pins: 137 PR5B/PCLKC2_0 (io), 139 PR5A/PCLKT2_0 (io), 140 PR4B (io), 141 PR4A (io), 142 PR3B (io), 143 PR3A (io), 153 PR2B/VREF1_2 (io), 154 PR2A/VREF2_2 (io)
part D pins: 107 PR14B/VREF2_3 (io), 108 PR14A/VREF1_3 (io), 109 PR13B (io), 110 PR13A (io), 111 PR12B (io), 112 PR12A (io), 113 PR11B (io), 114 PR11A/RDQS11 (io), 115 PR10B/RLM0_PLLC_FB_A (io), 117 PR10A/RLM0_PLLT_FB_A (io), 118 PR9B/RLM0_PLLC_IN_A (io), 119 PR9A/RLM0_PLLT_IN_A (io), 121 PR8B/DI/CSSPIN (io), 122 PR8A/DOUT/CSON (io), 123 PR7B/BUSY/SISPI (io), 124 PR7A/D7/SPID0 (io)
part E pins: 86 PB10A/WRITEN (io), 87 PB10B/CS1N (io), 88 PB11A/VREF1_4 (io), 89 PB11B/CSN (io), 90 PB12A/VREF2_4 (io), 91 PB12B/D0/SPID7 (io), 92 PB13A/D2/SPID5 (io), 94 PB13B/D1/SPID6 (io), 95 PB14A/BDQS14 (io), 96 PB14B/D3/SPID4 (io), 97 PB15A (io), 98 PB15B/D4/SPID3 (io), 99 PB16A (io), 100 PB16B/D5/SPID2 (io), 101 PB17A (io), 102 PB17B/D6/SPID1 (io)
part F pins: 65 PB2A (io), 66 PB2B (io), 67 PB3A (io), 68 PB3B (io), 69 PB4A (io), 70 PB4B (io), 71 PB5A (io), 73 PB5B (io), 75 PB6A/BDQS6 (io), 76 PB6B (io), 77 PB7A (io), 78 PB7B (io), 79 PB8A/VREF2_5 (io), 80 PB8B/VREF1_5 (io), 81 PB9A/PCLKT5_0 (io), 83 PB9B/PCLKC5_0 (io)
part G pins: 33 PL7A/LLM0_PLLT_IN_A (io), 34 PL7B/LLM0_PLLC_IN_A (io), 35 PL8A/LLM0_PLLT_FB_A (io), 36 PL8B/LLM0_PLLC_FB_A (io), 38 PL9A (io), 39 PL9B (io), 40 PL10A (io), 42 PL10B (io), 43 PL11A/LDQS11 (io), 44 PL11B (io), 45 PL12A (io), 46 PL12B (io), 47 PL13A (io), 48 PL13B (io), 49 PL14A/VREF1_6 (io), 50 PL14B/VREF2_6 (io)
part H pins: 3 PL2A/VREF2_7 (io), 4 PL2B/VREF1_7 (io), 15 PL3A (io), 16 PL3B (io), 17 PL4A (io), 19 PL4B (io), 20 PL5A/PCLKT7_0 (io), 21 PL5B/PCLKC7_0 (io)
part I pins: 23 XRES, 27 TCK (in), 29 TDI (in), 30 TMS (in), 31 TDO (out), 125 CFG2 (in), 126 CFG1 (in), 127 CFG0 (in), 129 PROGRAMN (in), 130 CCLK (io), 131 INITN (io), 133 DONE (io)
part J pins: 2 VCCIO7 (power), 26 VCC (power), 32 VCCJ (power), 37 VCCIO6 (power), 51 VCCIO6 (power), 53 VCCIO5 (power), 74 VCCIO5 (power), 84 VCCAUX (power), 85 VCCIO4 (power), 104 VCCIO4 (power), 106 VCCIO3 (power), 120 VCCIO3 (power), 128 VCC (power), 135 VCC (power), 155 VCCIO2 (power), 157 VCCIO1 (power), 176 VCCIO1 (power), 177 VCCAUX (power), 187 VCCIO0 (power), 208 VCCIO0 (power)
part K pins: 1 GND0-GND7 (power), 28 GND (power), 41 GND6 (power), 52 GND5-GND6 (power), 82 GND5 (power), 93 GND4 (power), 105 GND3-GND4 (power), 116 GND3 (power), 132 GND (power), 134 GND (power), 156 GND1-GND2 (power), 168 GND1 (power), 179 GND0 (power)
part L pins: 5 NC, 6 NC, 7 NC, 8 NC, 9 NC, 10 NC, 11 NC, 12 NC, 13 NC, 14 NC, 18 NC, 22 NC, 24 NC, 25 NC, 54 NC, 55 NC, 56 NC, 57 NC, 58 NC, 59 NC, 60 NC, 61 NC, 62 NC, 63 NC, 64 NC, 72 NC, 103 NC, 136 NC, 138 NC, 144 NC, 145 NC, 146 NC, 147 NC, 148 NC, 149 NC, 150 NC, 151 NC, 152 NC, 158 NC, 189 NC, 197 NC, 198 NC, 199 NC, 200 NC, 201 NC, 202 NC, 203 NC, 204 NC, 205 NC, 206 NC, 207 NC

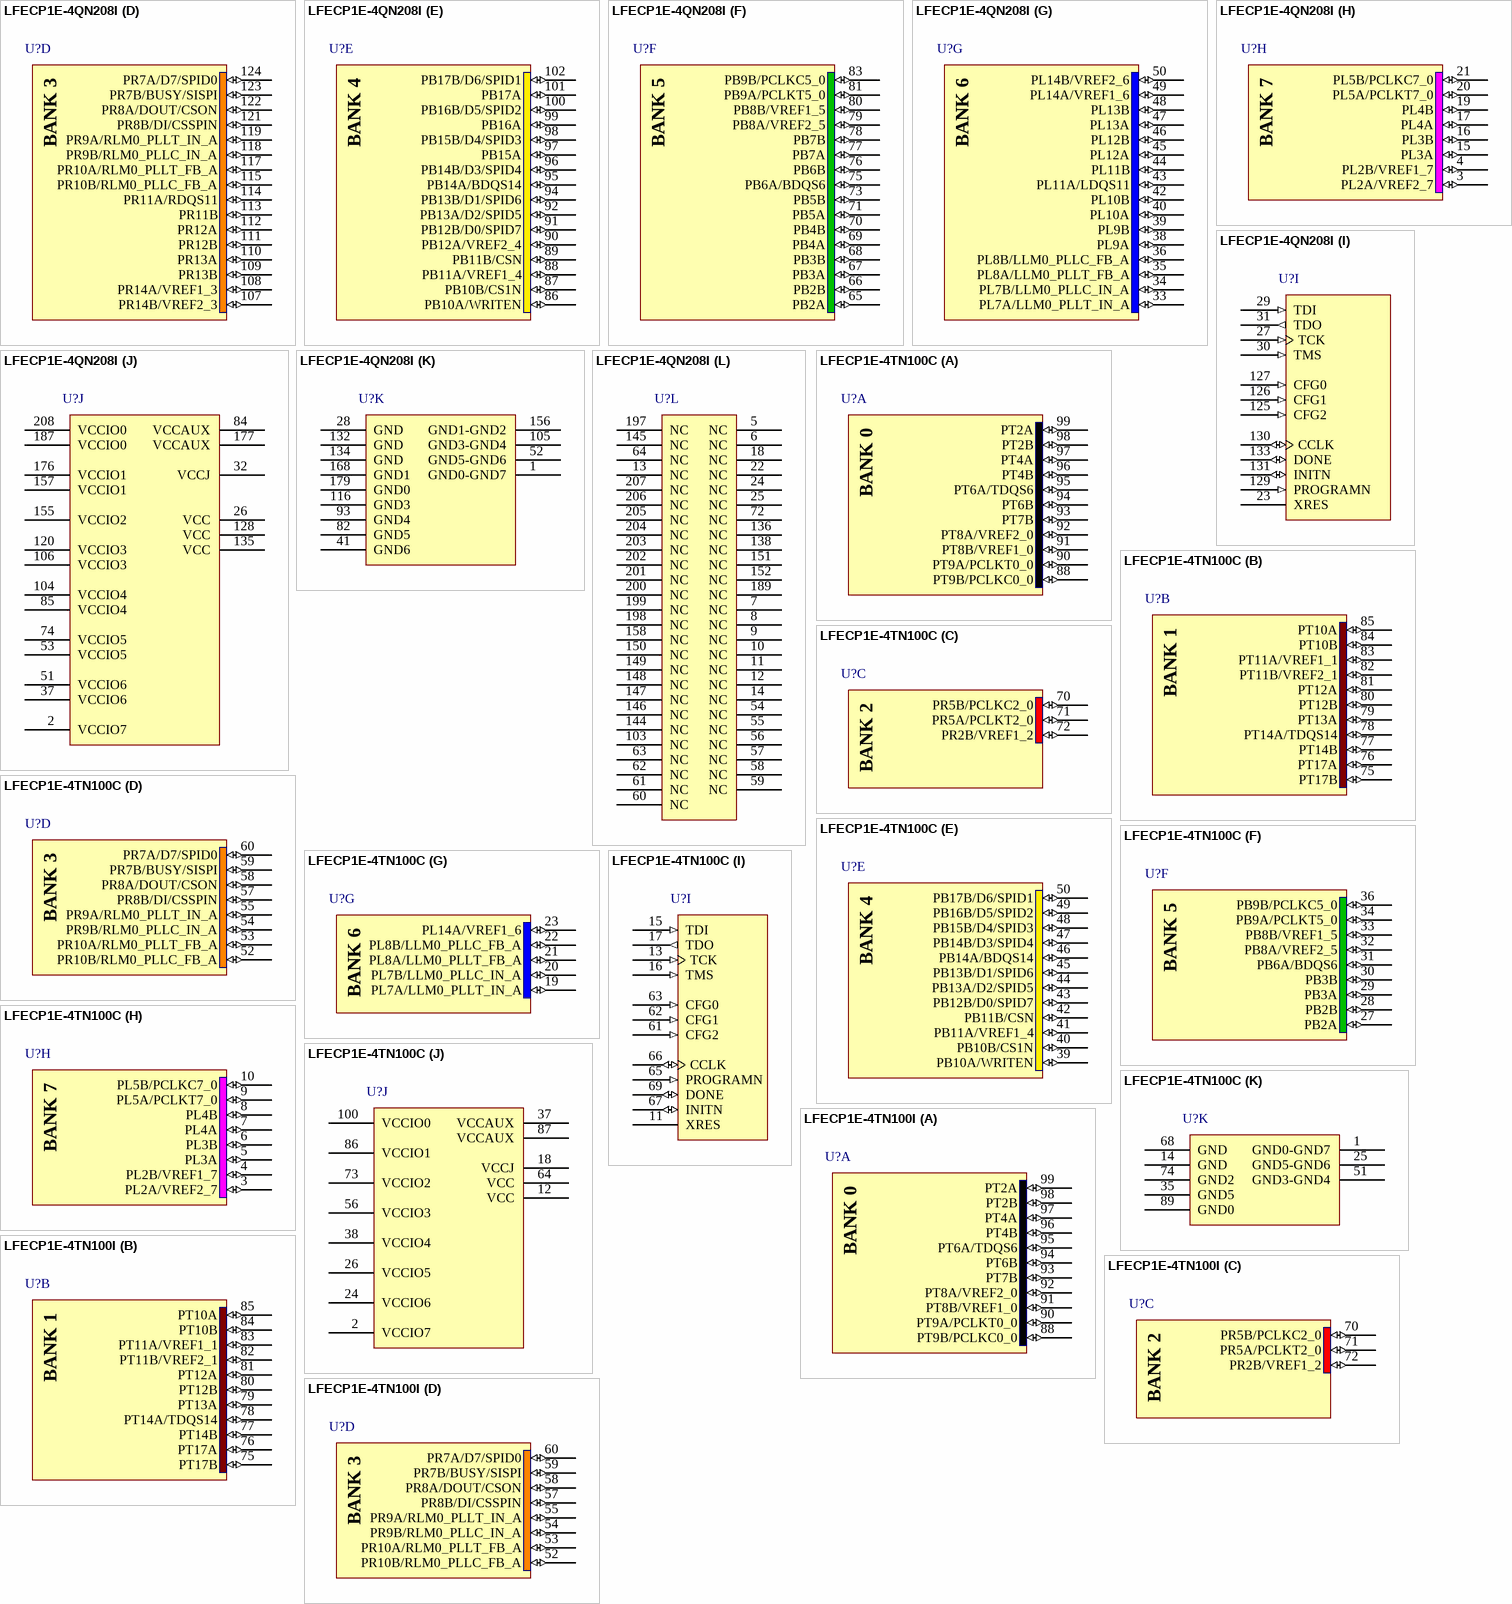
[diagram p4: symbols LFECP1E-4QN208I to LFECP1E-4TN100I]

## LFECP1E-4QN208I
designator U?
ECP 1.2V FPGA, 112 I/Os, 2 PLLs, 1.5K LUTs, 208-Pin PQFP, Pb-Free, Speed Grade 4, Industrial Temperature Grade; Note: Pins 1, 52, 105 and 156 are double bonded.; ComponentAvailability: Not Available
footprint PQFP208_N (Shrink QFP, 208-Leads, Body 28x28mm, Pitch 0.5mm, IPC Medium Density)
footprint PQFP208_L (Shrink QFP, 208-Leads, Body 28x28mm, Pitch 0.5mm, IPC High Density)
footprint PQFP208_M (Shrink QFP, 208-Leads, Body 28x28mm, Pitch 0.5mm, IPC Low Density)
3D model ECP1E-PQFP-208 (208-Pin Plastic Quad Flat Pack (PQFP208))
part A pins: 178 PT9B/PCLKC0_0 (io), 180 PT9A/PCLKT0_0 (io), 181 PT8B/VREF1_0 (io), 182 PT8A/VREF2_0 (io), 183 PT7B (io), 184 PT7A (io), 185 PT6B (io), 186 PT6A/TDQS6 (io), 188 PT5B (io), 190 PT5A (io), 191 PT4B (io), 192 PT4A (io), 193 PT3B (io), 194 PT3A (io), 195 PT2B (io), 196 PT2A (io)
part B pins: 159 PT17B (io), 160 PT17A (io), 161 PT16B (io), 162 PT16A (io), 163 PT15B (io), 164 PT15A (io), 165 PT14B (io), 166 PT14A/TDQS14 (io), 167 PT13B (io), 169 PT13A (io), 170 PT12B (io), 171 PT12A (io), 172 PT11B/VREF2_1 (io), 173 PT11A/VREF1_1 (io), 174 PT10B (io), 175 PT10A (io)
part C pins: 137 PR5B/PCLKC2_0 (io), 139 PR5A/PCLKT2_0 (io), 140 PR4B (io), 141 PR4A (io), 142 PR3B (io), 143 PR3A (io), 153 PR2B/VREF1_2 (io), 154 PR2A/VREF2_2 (io)
part D pins: 107 PR14B/VREF2_3 (io), 108 PR14A/VREF1_3 (io), 109 PR13B (io), 110 PR13A (io), 111 PR12B (io), 112 PR12A (io), 113 PR11B (io), 114 PR11A/RDQS11 (io), 115 PR10B/RLM0_PLLC_FB_A (io), 117 PR10A/RLM0_PLLT_FB_A (io), 118 PR9B/RLM0_PLLC_IN_A (io), 119 PR9A/RLM0_PLLT_IN_A (io), 121 PR8B/DI/CSSPIN (io), 122 PR8A/DOUT/CSON (io), 123 PR7B/BUSY/SISPI (io), 124 PR7A/D7/SPID0 (io)
part E pins: 86 PB10A/WRITEN (io), 87 PB10B/CS1N (io), 88 PB11A/VREF1_4 (io), 89 PB11B/CSN (io), 90 PB12A/VREF2_4 (io), 91 PB12B/D0/SPID7 (io), 92 PB13A/D2/SPID5 (io), 94 PB13B/D1/SPID6 (io), 95 PB14A/BDQS14 (io), 96 PB14B/D3/SPID4 (io), 97 PB15A (io), 98 PB15B/D4/SPID3 (io), 99 PB16A (io), 100 PB16B/D5/SPID2 (io), 101 PB17A (io), 102 PB17B/D6/SPID1 (io)
part F pins: 65 PB2A (io), 66 PB2B (io), 67 PB3A (io), 68 PB3B (io), 69 PB4A (io), 70 PB4B (io), 71 PB5A (io), 73 PB5B (io), 75 PB6A/BDQS6 (io), 76 PB6B (io), 77 PB7A (io), 78 PB7B (io), 79 PB8A/VREF2_5 (io), 80 PB8B/VREF1_5 (io), 81 PB9A/PCLKT5_0 (io), 83 PB9B/PCLKC5_0 (io)
part G pins: 33 PL7A/LLM0_PLLT_IN_A (io), 34 PL7B/LLM0_PLLC_IN_A (io), 35 PL8A/LLM0_PLLT_FB_A (io), 36 PL8B/LLM0_PLLC_FB_A (io), 38 PL9A (io), 39 PL9B (io), 40 PL10A (io), 42 PL10B (io), 43 PL11A/LDQS11 (io), 44 PL11B (io), 45 PL12A (io), 46 PL12B (io), 47 PL13A (io), 48 PL13B (io), 49 PL14A/VREF1_6 (io), 50 PL14B/VREF2_6 (io)
part H pins: 3 PL2A/VREF2_7 (io), 4 PL2B/VREF1_7 (io), 15 PL3A (io), 16 PL3B (io), 17 PL4A (io), 19 PL4B (io), 20 PL5A/PCLKT7_0 (io), 21 PL5B/PCLKC7_0 (io)
part I pins: 23 XRES, 27 TCK (in), 29 TDI (in), 30 TMS (in), 31 TDO (out), 125 CFG2 (in), 126 CFG1 (in), 127 CFG0 (in), 129 PROGRAMN (in), 130 CCLK (io), 131 INITN (io), 133 DONE (io)
part J pins: 2 VCCIO7 (power), 26 VCC (power), 32 VCCJ (power), 37 VCCIO6 (power), 51 VCCIO6 (power), 53 VCCIO5 (power), 74 VCCIO5 (power), 84 VCCAUX (power), 85 VCCIO4 (power), 104 VCCIO4 (power), 106 VCCIO3 (power), 120 VCCIO3 (power), 128 VCC (power), 135 VCC (power), 155 VCCIO2 (power), 157 VCCIO1 (power), 176 VCCIO1 (power), 177 VCCAUX (power), 187 VCCIO0 (power), 208 VCCIO0 (power)
part K pins: 1 GND0-GND7 (power), 28 GND (power), 41 GND6 (power), 52 GND5-GND6 (power), 82 GND5 (power), 93 GND4 (power), 105 GND3-GND4 (power), 116 GND3 (power), 132 GND (power), 134 GND (power), 156 GND1-GND2 (power), 168 GND1 (power), 179 GND0 (power)
part L pins: 5 NC, 6 NC, 7 NC, 8 NC, 9 NC, 10 NC, 11 NC, 12 NC, 13 NC, 14 NC, 18 NC, 22 NC, 24 NC, 25 NC, 54 NC, 55 NC, 56 NC, 57 NC, 58 NC, 59 NC, 60 NC, 61 NC, 62 NC, 63 NC, 64 NC, 72 NC, 103 NC, 136 NC, 138 NC, 144 NC, 145 NC, 146 NC, 147 NC, 148 NC, 149 NC, 150 NC, 151 NC, 152 NC, 158 NC, 189 NC, 197 NC, 198 NC, 199 NC, 200 NC, 201 NC, 202 NC, 203 NC, 204 NC, 205 NC, 206 NC, 207 NC

## LFECP1E-4TN100C
designator U?
ECP 1.2V FPGA, 67 I/Os, 2 PLLs, 1.5K LUTs, 100-Pin TQFP, Pb-Free, Speed Grade 4, Commercial Temperature Grade; Note: Pins 1, 25 and 51 are double bonded.; ComponentAvailability: Not Available
footprint TQFP100_N (Thin QFP, 100-Leads, Body 14x14mm, Pitch 0.5mm, IPC Medium Density)
footprint TQFP100_L (Thin QFP, 100-Leads, Body 14x14mm, Pitch 0.5mm, IPC High Density)
footprint TQFP100_M (Thin QFP, 100-Leads, Body 14x14mm, Pitch 0.5mm, IPC Low Density)
3D model ECP1E-TQFP-100 (100-Pin Thin Quad Flat Pack (TQFP100))
part A pins: 88 PT9B/PCLKC0_0 (io), 90 PT9A/PCLKT0_0 (io), 91 PT8B/VREF1_0 (io), 92 PT8A/VREF2_0 (io), 93 PT7B (io), 94 PT6B (io), 95 PT6A/TDQS6 (io), 96 PT4B (io), 97 PT4A (io), 98 PT2B (io), 99 PT2A (io)
part B pins: 75 PT17B (io), 76 PT17A (io), 77 PT14B (io), 78 PT14A/TDQS14 (io), 79 PT13A (io), 80 PT12B (io), 81 PT12A (io), 82 PT11B/VREF2_1 (io), 83 PT11A/VREF1_1 (io), 84 PT10B (io), 85 PT10A (io)
part C pins: 70 PR5B/PCLKC2_0 (io), 71 PR5A/PCLKT2_0 (io), 72 PR2B/VREF1_2 (io)
part D pins: 52 PR10B/RLM0_PLLC_FB_A (io), 53 PR10A/RLM0_PLLT_FB_A (io), 54 PR9B/RLM0_PLLC_IN_A (io), 55 PR9A/RLM0_PLLT_IN_A (io), 57 PR8B/DI/CSSPIN (io), 58 PR8A/DOUT/CSON (io), 59 PR7B/BUSY/SISPI (io), 60 PR7A/D7/SPID0 (io)
part E pins: 39 PB10A/WRITEN (io), 40 PB10B/CS1N (io), 41 PB11A/VREF1_4 (io), 42 PB11B/CSN (io), 43 PB12B/D0/SPID7 (io), 44 PB13A/D2/SPID5 (io), 45 PB13B/D1/SPID6 (io), 46 PB14A/BDQS14 (io), 47 PB14B/D3/SPID4 (io), 48 PB15B/D4/SPID3 (io), 49 PB16B/D5/SPID2 (io), 50 PB17B/D6/SPID1 (io)
part F pins: 27 PB2A (io), 28 PB2B (io), 29 PB3A (io), 30 PB3B (io), 31 PB6A/BDQS6 (io), 32 PB8A/VREF2_5 (io), 33 PB8B/VREF1_5 (io), 34 PB9A/PCLKT5_0 (io), 36 PB9B/PCLKC5_0 (io)
part G pins: 19 PL7A/LLM0_PLLT_IN_A (io), 20 PL7B/LLM0_PLLC_IN_A (io), 21 PL8A/LLM0_PLLT_FB_A (io), 22 PL8B/LLM0_PLLC_FB_A (io), 23 PL14A/VREF1_6 (io)
part H pins: 3 PL2A/VREF2_7 (io), 4 PL2B/VREF1_7 (io), 5 PL3A (io), 6 PL3B (io), 7 PL4A (io), 8 PL4B (io), 9 PL5A/PCLKT7_0 (io), 10 PL5B/PCLKC7_0 (io)
part I pins: 11 XRES, 13 TCK (in), 15 TDI (in), 16 TMS (in), 17 TDO (out), 61 CFG2 (in), 62 CFG1 (in), 63 CFG0 (in), 65 PROGRAMN (in), 66 CCLK (io), 67 INITN (io), 69 DONE (io)
part J pins: 2 VCCIO7 (power), 12 VCC (power), 18 VCCJ (power), 24 VCCIO6 (power), 26 VCCIO5 (power), 37 VCCAUX (power), 38 VCCIO4 (power), 56 VCCIO3 (power), 64 VCC (power), 73 VCCIO2 (power), 86 VCCIO1 (power), 87 VCCAUX (power), 100 VCCIO0 (power)
part K pins: 1 GND0-GND7 (power), 14 GND (power), 25 GND5-GND6 (power), 35 GND5 (power), 51 GND3-GND4 (power), 68 GND (power), 74 GND2 (power), 89 GND0 (power)

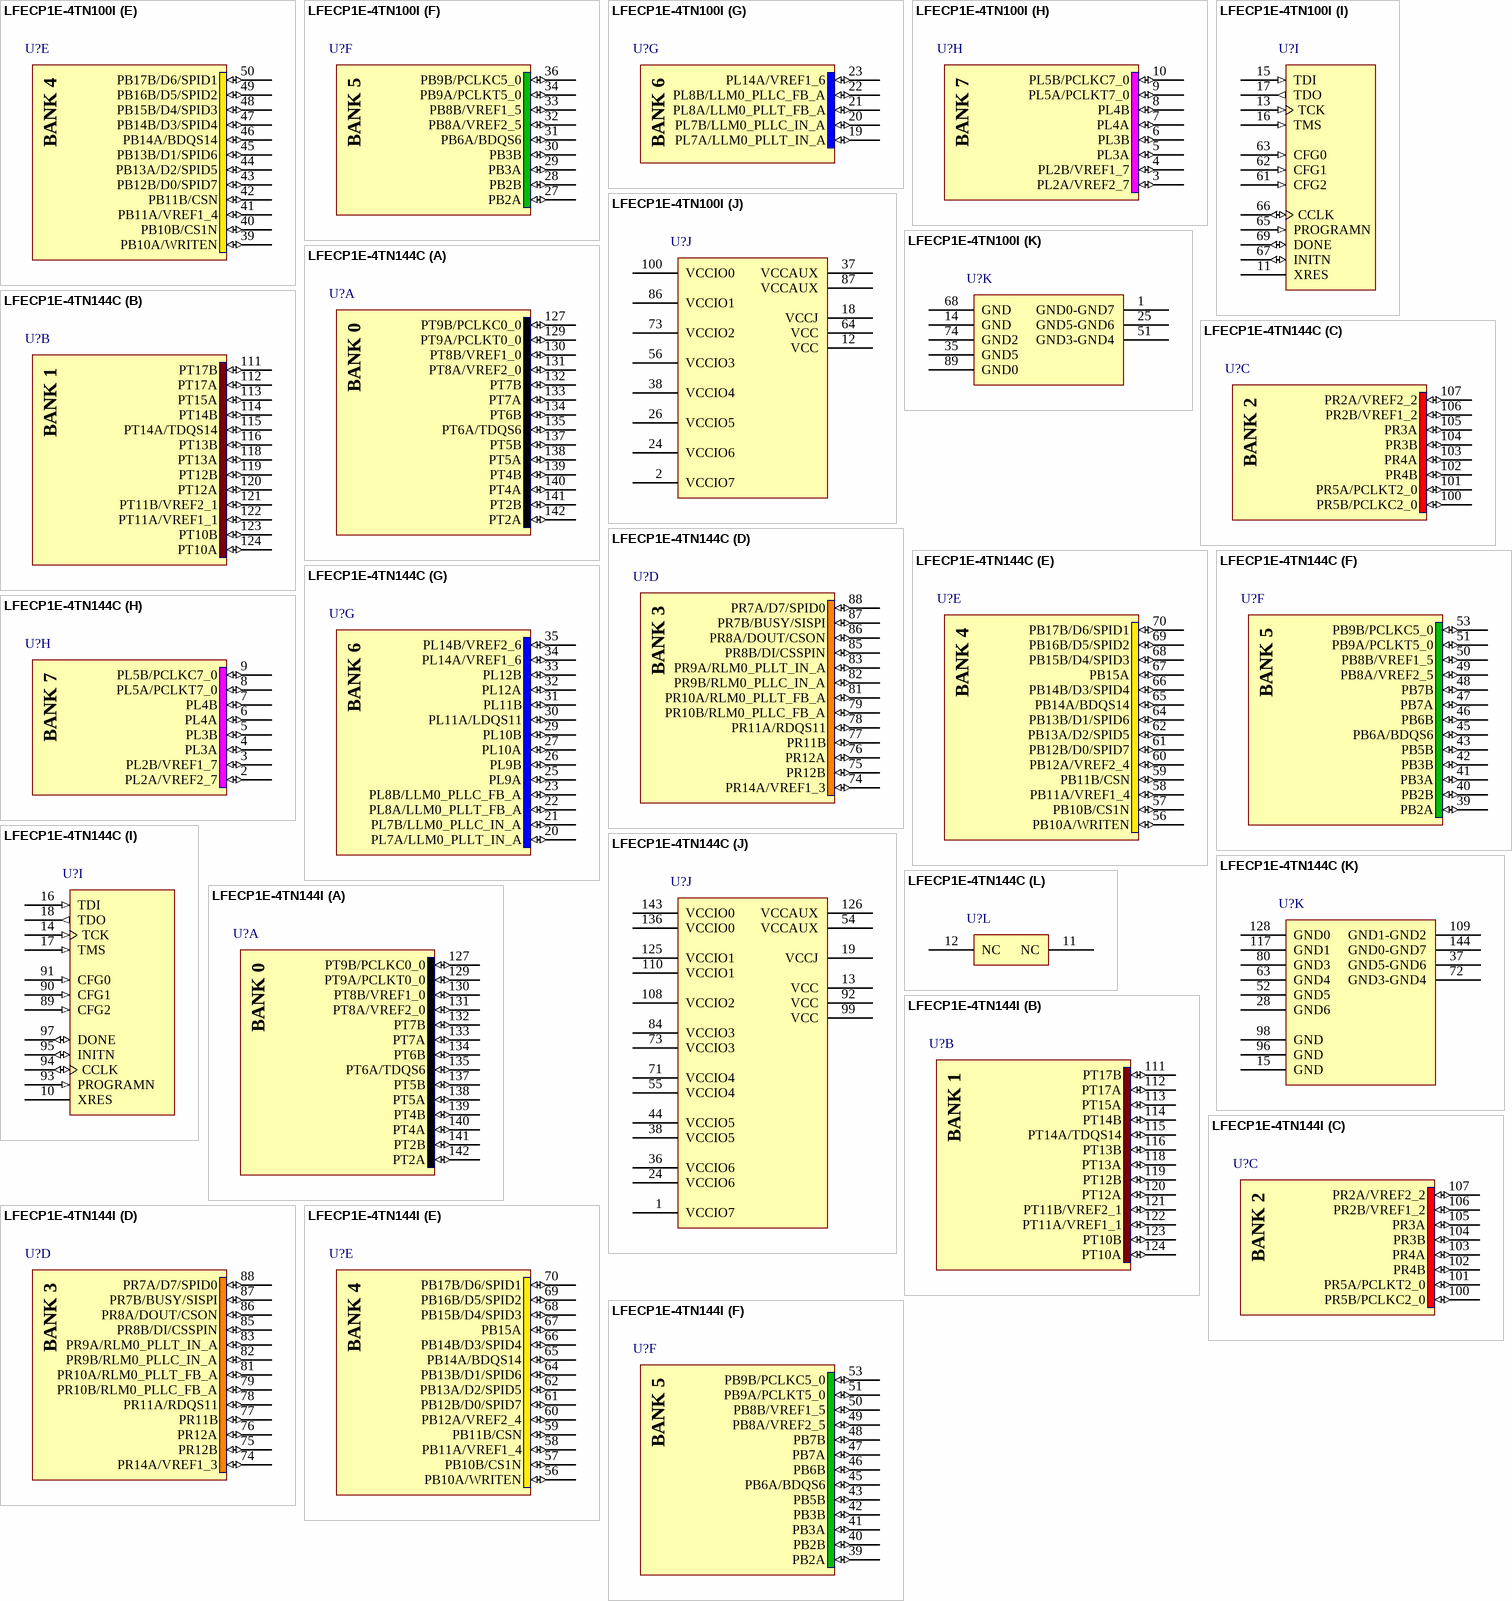
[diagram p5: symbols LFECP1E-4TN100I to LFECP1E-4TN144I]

## LFECP1E-4TN100I
designator U?
ECP 1.2V FPGA, 67 I/Os, 2 PLLs, 1.5K LUTs, 100-Pin TQFP, Pb-Free, Speed Grade 4, Industrial Temperature Grade; Note: Pins 1, 25 and 51 are double bonded.; ComponentAvailability: Not Available
footprint TQFP100_N (Thin QFP, 100-Leads, Body 14x14mm, Pitch 0.5mm, IPC Medium Density)
footprint TQFP100_L (Thin QFP, 100-Leads, Body 14x14mm, Pitch 0.5mm, IPC High Density)
footprint TQFP100_M (Thin QFP, 100-Leads, Body 14x14mm, Pitch 0.5mm, IPC Low Density)
3D model ECP1E-TQFP-100 (100-Pin Thin Quad Flat Pack (TQFP100))
part A pins: 88 PT9B/PCLKC0_0 (io), 90 PT9A/PCLKT0_0 (io), 91 PT8B/VREF1_0 (io), 92 PT8A/VREF2_0 (io), 93 PT7B (io), 94 PT6B (io), 95 PT6A/TDQS6 (io), 96 PT4B (io), 97 PT4A (io), 98 PT2B (io), 99 PT2A (io)
part B pins: 75 PT17B (io), 76 PT17A (io), 77 PT14B (io), 78 PT14A/TDQS14 (io), 79 PT13A (io), 80 PT12B (io), 81 PT12A (io), 82 PT11B/VREF2_1 (io), 83 PT11A/VREF1_1 (io), 84 PT10B (io), 85 PT10A (io)
part C pins: 70 PR5B/PCLKC2_0 (io), 71 PR5A/PCLKT2_0 (io), 72 PR2B/VREF1_2 (io)
part D pins: 52 PR10B/RLM0_PLLC_FB_A (io), 53 PR10A/RLM0_PLLT_FB_A (io), 54 PR9B/RLM0_PLLC_IN_A (io), 55 PR9A/RLM0_PLLT_IN_A (io), 57 PR8B/DI/CSSPIN (io), 58 PR8A/DOUT/CSON (io), 59 PR7B/BUSY/SISPI (io), 60 PR7A/D7/SPID0 (io)
part E pins: 39 PB10A/WRITEN (io), 40 PB10B/CS1N (io), 41 PB11A/VREF1_4 (io), 42 PB11B/CSN (io), 43 PB12B/D0/SPID7 (io), 44 PB13A/D2/SPID5 (io), 45 PB13B/D1/SPID6 (io), 46 PB14A/BDQS14 (io), 47 PB14B/D3/SPID4 (io), 48 PB15B/D4/SPID3 (io), 49 PB16B/D5/SPID2 (io), 50 PB17B/D6/SPID1 (io)
part F pins: 27 PB2A (io), 28 PB2B (io), 29 PB3A (io), 30 PB3B (io), 31 PB6A/BDQS6 (io), 32 PB8A/VREF2_5 (io), 33 PB8B/VREF1_5 (io), 34 PB9A/PCLKT5_0 (io), 36 PB9B/PCLKC5_0 (io)
part G pins: 19 PL7A/LLM0_PLLT_IN_A (io), 20 PL7B/LLM0_PLLC_IN_A (io), 21 PL8A/LLM0_PLLT_FB_A (io), 22 PL8B/LLM0_PLLC_FB_A (io), 23 PL14A/VREF1_6 (io)
part H pins: 3 PL2A/VREF2_7 (io), 4 PL2B/VREF1_7 (io), 5 PL3A (io), 6 PL3B (io), 7 PL4A (io), 8 PL4B (io), 9 PL5A/PCLKT7_0 (io), 10 PL5B/PCLKC7_0 (io)
part I pins: 11 XRES, 13 TCK (in), 15 TDI (in), 16 TMS (in), 17 TDO (out), 61 CFG2 (in), 62 CFG1 (in), 63 CFG0 (in), 65 PROGRAMN (in), 66 CCLK (io), 67 INITN (io), 69 DONE (io)
part J pins: 2 VCCIO7 (power), 12 VCC (power), 18 VCCJ (power), 24 VCCIO6 (power), 26 VCCIO5 (power), 37 VCCAUX (power), 38 VCCIO4 (power), 56 VCCIO3 (power), 64 VCC (power), 73 VCCIO2 (power), 86 VCCIO1 (power), 87 VCCAUX (power), 100 VCCIO0 (power)
part K pins: 1 GND0-GND7 (power), 14 GND (power), 25 GND5-GND6 (power), 35 GND5 (power), 51 GND3-GND4 (power), 68 GND (power), 74 GND2 (power), 89 GND0 (power)

## LFECP1E-4TN144C
designator U?
ECP 1.2V FPGA, 97 I/Os, 2 PLLs, 1.5K LUTs, 144-Pin TQFP, Pb-Free, Speed Grade 4, Commercial Temperature Grade; Note: Pins 37, 72, 109 and 144 are double bonded.; ComponentAvailability: Not Available
footprint TQFP144_N (Thin QFP, 144-Leads, Body 20x20mm, Pitch 0.5mm, IPC Medium Density)
footprint TQFP144_L (Thin QFP, 144-Leads, Body 20x20mm, Pitch 0.5mm, IPC High Density)
footprint TQFP144_M (Thin QFP, 144-Leads, Body 20x20mm, Pitch 0.5mm, IPC Low Density)
3D model ECP1E-TQFP-144 (144-Pin Thin Quad Flat Pack (TQFP144))
part A pins: 127 PT9B/PCLKC0_0 (io), 129 PT9A/PCLKT0_0 (io), 130 PT8B/VREF1_0 (io), 131 PT8A/VREF2_0 (io), 132 PT7B (io), 133 PT7A (io), 134 PT6B (io), 135 PT6A/TDQS6 (io), 137 PT5B (io), 138 PT5A (io), 139 PT4B (io), 140 PT4A (io), 141 PT2B (io), 142 PT2A (io)
part B pins: 111 PT17B (io), 112 PT17A (io), 113 PT15A (io), 114 PT14B (io), 115 PT14A/TDQS14 (io), 116 PT13B (io), 118 PT13A (io), 119 PT12B (io), 120 PT12A (io), 121 PT11B/VREF2_1 (io), 122 PT11A/VREF1_1 (io), 123 PT10B (io), 124 PT10A (io)
part C pins: 100 PR5B/PCLKC2_0 (io), 101 PR5A/PCLKT2_0 (io), 102 PR4B (io), 103 PR4A (io), 104 PR3B (io), 105 PR3A (io), 106 PR2B/VREF1_2 (io), 107 PR2A/VREF2_2 (io)
part D pins: 74 PR14A/VREF1_3 (io), 75 PR12B (io), 76 PR12A (io), 77 PR11B (io), 78 PR11A/RDQS11 (io), 79 PR10B/RLM0_PLLC_FB_A (io), 81 PR10A/RLM0_PLLT_FB_A (io), 82 PR9B/RLM0_PLLC_IN_A (io), 83 PR9A/RLM0_PLLT_IN_A (io), 85 PR8B/DI/CSSPIN (io), 86 PR8A/DOUT/CSON (io), 87 PR7B/BUSY/SISPI (io), 88 PR7A/D7/SPID0 (io)
part E pins: 56 PB10A/WRITEN (io), 57 PB10B/CS1N (io), 58 PB11A/VREF1_4 (io), 59 PB11B/CSN (io), 60 PB12A/VREF2_4 (io), 61 PB12B/D0/SPID7 (io), 62 PB13A/D2/SPID5 (io), 64 PB13B/D1/SPID6 (io), 65 PB14A/BDQS14 (io), 66 PB14B/D3/SPID4 (io), 67 PB15A (io), 68 PB15B/D4/SPID3 (io), 69 PB16B/D5/SPID2 (io), 70 PB17B/D6/SPID1 (io)
part F pins: 39 PB2A (io), 40 PB2B (io), 41 PB3A (io), 42 PB3B (io), 43 PB5B (io), 45 PB6A/BDQS6 (io), 46 PB6B (io), 47 PB7A (io), 48 PB7B (io), 49 PB8A/VREF2_5 (io), 50 PB8B/VREF1_5 (io), 51 PB9A/PCLKT5_0 (io), 53 PB9B/PCLKC5_0 (io)
part G pins: 20 PL7A/LLM0_PLLT_IN_A (io), 21 PL7B/LLM0_PLLC_IN_A (io), 22 PL8A/LLM0_PLLT_FB_A (io), 23 PL8B/LLM0_PLLC_FB_A (io), 25 PL9A (io), 26 PL9B (io), 27 PL10A (io), 29 PL10B (io), 30 PL11A/LDQS11 (io), 31 PL11B (io), 32 PL12A (io), 33 PL12B (io), 34 PL14A/VREF1_6 (io), 35 PL14B/VREF2_6 (io)
part H pins: 2 PL2A/VREF2_7 (io), 3 PL2B/VREF1_7 (io), 4 PL3A (io), 5 PL3B (io), 6 PL4A (io), 7 PL4B (io), 8 PL5A/PCLKT7_0 (io), 9 PL5B/PCLKC7_0 (io)
part I pins: 10 XRES, 14 TCK (in), 16 TDI (in), 17 TMS (in), 18 TDO (out), 89 CFG2 (in), 90 CFG1 (in), 91 CFG0 (in), 93 PROGRAMN (in), 94 CCLK (io), 95 INITN (io), 97 DONE (io)
part J pins: 1 VCCIO7 (power), 13 VCC (power), 19 VCCJ (power), 24 VCCIO6 (power), 36 VCCIO6 (power), 38 VCCIO5 (power), 44 VCCIO5 (power), 54 VCCAUX (power), 55 VCCIO4 (power), 71 VCCIO4 (power), 73 VCCIO3 (power), 84 VCCIO3 (power), 92 VCC (power), 99 VCC (power), 108 VCCIO2 (power), 110 VCCIO1 (power), 125 VCCIO1 (power), 126 VCCAUX (power), 136 VCCIO0 (power), 143 VCCIO0 (power)
part K pins: 15 GND (power), 28 GND6 (power), 37 GND5-GND6 (power), 52 GND5 (power), 63 GND4 (power), 72 GND3-GND4 (power), 80 GND3 (power), 96 GND (power), 98 GND (power), 109 GND1-GND2 (power), 117 GND1 (power), 128 GND0 (power), 144 GND0-GND7 (power)
part L pins: 11 NC, 12 NC

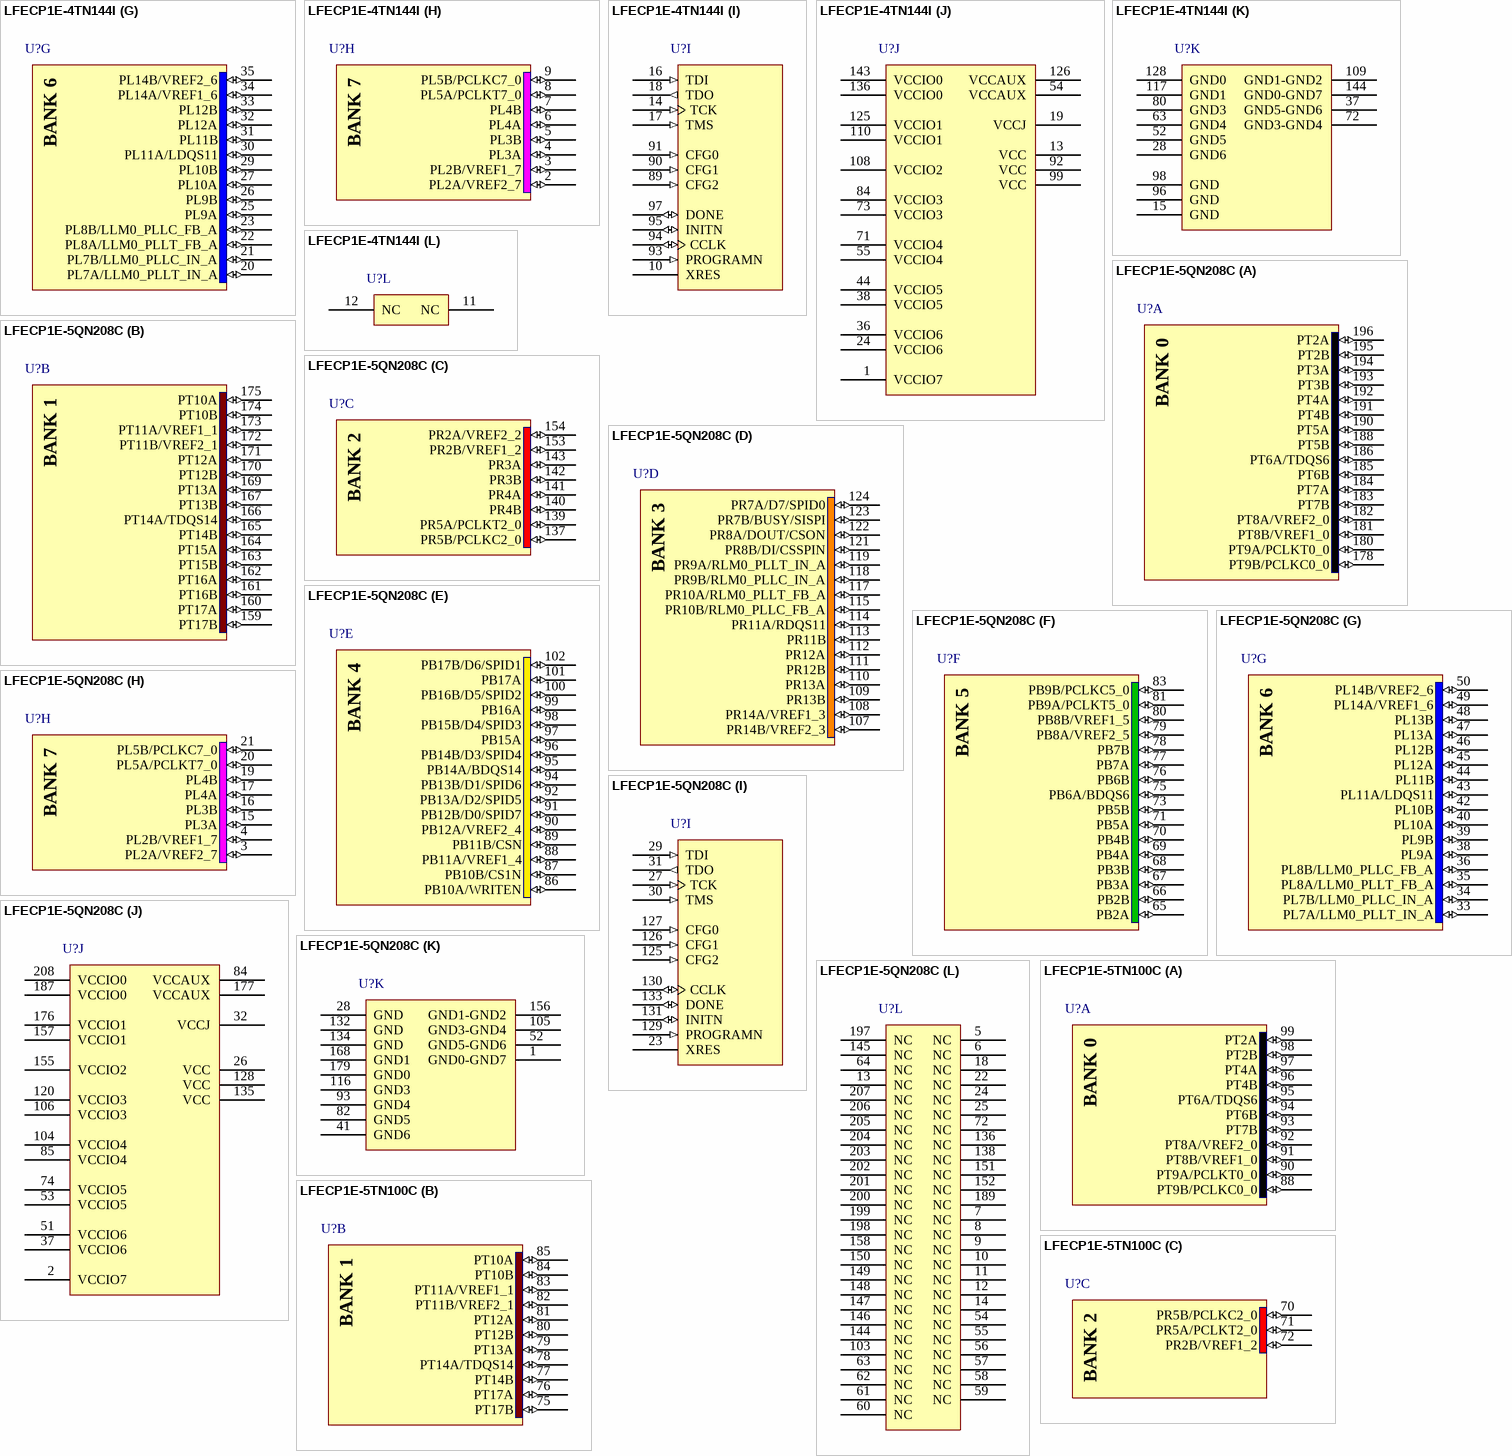
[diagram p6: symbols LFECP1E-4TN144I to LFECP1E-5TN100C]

## LFECP1E-4TN144I
designator U?
ECP 1.2V FPGA, 97 I/Os, 2 PLLs, 1.5K LUTs, 144-Pin TQFP, Pb-Free, Speed Grade 4, Industrial Temperature Grade; Note: Pins 37, 72, 109 and 144 are double bonded.; ComponentAvailability: Not Available
footprint TQFP144_N (Thin QFP, 144-Leads, Body 20x20mm, Pitch 0.5mm, IPC Medium Density)
footprint TQFP144_L (Thin QFP, 144-Leads, Body 20x20mm, Pitch 0.5mm, IPC High Density)
footprint TQFP144_M (Thin QFP, 144-Leads, Body 20x20mm, Pitch 0.5mm, IPC Low Density)
3D model ECP1E-TQFP-144 (144-Pin Thin Quad Flat Pack (TQFP144))
part A pins: 127 PT9B/PCLKC0_0 (io), 129 PT9A/PCLKT0_0 (io), 130 PT8B/VREF1_0 (io), 131 PT8A/VREF2_0 (io), 132 PT7B (io), 133 PT7A (io), 134 PT6B (io), 135 PT6A/TDQS6 (io), 137 PT5B (io), 138 PT5A (io), 139 PT4B (io), 140 PT4A (io), 141 PT2B (io), 142 PT2A (io)
part B pins: 111 PT17B (io), 112 PT17A (io), 113 PT15A (io), 114 PT14B (io), 115 PT14A/TDQS14 (io), 116 PT13B (io), 118 PT13A (io), 119 PT12B (io), 120 PT12A (io), 121 PT11B/VREF2_1 (io), 122 PT11A/VREF1_1 (io), 123 PT10B (io), 124 PT10A (io)
part C pins: 100 PR5B/PCLKC2_0 (io), 101 PR5A/PCLKT2_0 (io), 102 PR4B (io), 103 PR4A (io), 104 PR3B (io), 105 PR3A (io), 106 PR2B/VREF1_2 (io), 107 PR2A/VREF2_2 (io)
part D pins: 74 PR14A/VREF1_3 (io), 75 PR12B (io), 76 PR12A (io), 77 PR11B (io), 78 PR11A/RDQS11 (io), 79 PR10B/RLM0_PLLC_FB_A (io), 81 PR10A/RLM0_PLLT_FB_A (io), 82 PR9B/RLM0_PLLC_IN_A (io), 83 PR9A/RLM0_PLLT_IN_A (io), 85 PR8B/DI/CSSPIN (io), 86 PR8A/DOUT/CSON (io), 87 PR7B/BUSY/SISPI (io), 88 PR7A/D7/SPID0 (io)
part E pins: 56 PB10A/WRITEN (io), 57 PB10B/CS1N (io), 58 PB11A/VREF1_4 (io), 59 PB11B/CSN (io), 60 PB12A/VREF2_4 (io), 61 PB12B/D0/SPID7 (io), 62 PB13A/D2/SPID5 (io), 64 PB13B/D1/SPID6 (io), 65 PB14A/BDQS14 (io), 66 PB14B/D3/SPID4 (io), 67 PB15A (io), 68 PB15B/D4/SPID3 (io), 69 PB16B/D5/SPID2 (io), 70 PB17B/D6/SPID1 (io)
part F pins: 39 PB2A (io), 40 PB2B (io), 41 PB3A (io), 42 PB3B (io), 43 PB5B (io), 45 PB6A/BDQS6 (io), 46 PB6B (io), 47 PB7A (io), 48 PB7B (io), 49 PB8A/VREF2_5 (io), 50 PB8B/VREF1_5 (io), 51 PB9A/PCLKT5_0 (io), 53 PB9B/PCLKC5_0 (io)
part G pins: 20 PL7A/LLM0_PLLT_IN_A (io), 21 PL7B/LLM0_PLLC_IN_A (io), 22 PL8A/LLM0_PLLT_FB_A (io), 23 PL8B/LLM0_PLLC_FB_A (io), 25 PL9A (io), 26 PL9B (io), 27 PL10A (io), 29 PL10B (io), 30 PL11A/LDQS11 (io), 31 PL11B (io), 32 PL12A (io), 33 PL12B (io), 34 PL14A/VREF1_6 (io), 35 PL14B/VREF2_6 (io)
part H pins: 2 PL2A/VREF2_7 (io), 3 PL2B/VREF1_7 (io), 4 PL3A (io), 5 PL3B (io), 6 PL4A (io), 7 PL4B (io), 8 PL5A/PCLKT7_0 (io), 9 PL5B/PCLKC7_0 (io)
part I pins: 10 XRES, 14 TCK (in), 16 TDI (in), 17 TMS (in), 18 TDO (out), 89 CFG2 (in), 90 CFG1 (in), 91 CFG0 (in), 93 PROGRAMN (in), 94 CCLK (io), 95 INITN (io), 97 DONE (io)
part J pins: 1 VCCIO7 (power), 13 VCC (power), 19 VCCJ (power), 24 VCCIO6 (power), 36 VCCIO6 (power), 38 VCCIO5 (power), 44 VCCIO5 (power), 54 VCCAUX (power), 55 VCCIO4 (power), 71 VCCIO4 (power), 73 VCCIO3 (power), 84 VCCIO3 (power), 92 VCC (power), 99 VCC (power), 108 VCCIO2 (power), 110 VCCIO1 (power), 125 VCCIO1 (power), 126 VCCAUX (power), 136 VCCIO0 (power), 143 VCCIO0 (power)
part K pins: 15 GND (power), 28 GND6 (power), 37 GND5-GND6 (power), 52 GND5 (power), 63 GND4 (power), 72 GND3-GND4 (power), 80 GND3 (power), 96 GND (power), 98 GND (power), 109 GND1-GND2 (power), 117 GND1 (power), 128 GND0 (power), 144 GND0-GND7 (power)
part L pins: 11 NC, 12 NC

## LFECP1E-5QN208C
designator U?
ECP 1.2V FPGA, 112 I/Os, 2 PLLs, 1.5K LUTs, 208-Pin PQFP, Pb-Free, Speed Grade 5, Commercial Temperature Grade; Note: Pins 1, 52, 105 and 156 are double bonded.; ComponentAvailability: Not Available
footprint PQFP208_N (Shrink QFP, 208-Leads, Body 28x28mm, Pitch 0.5mm, IPC Medium Density)
footprint PQFP208_L (Shrink QFP, 208-Leads, Body 28x28mm, Pitch 0.5mm, IPC High Density)
footprint PQFP208_M (Shrink QFP, 208-Leads, Body 28x28mm, Pitch 0.5mm, IPC Low Density)
3D model ECP1E-PQFP-208 (208-Pin Plastic Quad Flat Pack (PQFP208))
part A pins: 178 PT9B/PCLKC0_0 (io), 180 PT9A/PCLKT0_0 (io), 181 PT8B/VREF1_0 (io), 182 PT8A/VREF2_0 (io), 183 PT7B (io), 184 PT7A (io), 185 PT6B (io), 186 PT6A/TDQS6 (io), 188 PT5B (io), 190 PT5A (io), 191 PT4B (io), 192 PT4A (io), 193 PT3B (io), 194 PT3A (io), 195 PT2B (io), 196 PT2A (io)
part B pins: 159 PT17B (io), 160 PT17A (io), 161 PT16B (io), 162 PT16A (io), 163 PT15B (io), 164 PT15A (io), 165 PT14B (io), 166 PT14A/TDQS14 (io), 167 PT13B (io), 169 PT13A (io), 170 PT12B (io), 171 PT12A (io), 172 PT11B/VREF2_1 (io), 173 PT11A/VREF1_1 (io), 174 PT10B (io), 175 PT10A (io)
part C pins: 137 PR5B/PCLKC2_0 (io), 139 PR5A/PCLKT2_0 (io), 140 PR4B (io), 141 PR4A (io), 142 PR3B (io), 143 PR3A (io), 153 PR2B/VREF1_2 (io), 154 PR2A/VREF2_2 (io)
part D pins: 107 PR14B/VREF2_3 (io), 108 PR14A/VREF1_3 (io), 109 PR13B (io), 110 PR13A (io), 111 PR12B (io), 112 PR12A (io), 113 PR11B (io), 114 PR11A/RDQS11 (io), 115 PR10B/RLM0_PLLC_FB_A (io), 117 PR10A/RLM0_PLLT_FB_A (io), 118 PR9B/RLM0_PLLC_IN_A (io), 119 PR9A/RLM0_PLLT_IN_A (io), 121 PR8B/DI/CSSPIN (io), 122 PR8A/DOUT/CSON (io), 123 PR7B/BUSY/SISPI (io), 124 PR7A/D7/SPID0 (io)
part E pins: 86 PB10A/WRITEN (io), 87 PB10B/CS1N (io), 88 PB11A/VREF1_4 (io), 89 PB11B/CSN (io), 90 PB12A/VREF2_4 (io), 91 PB12B/D0/SPID7 (io), 92 PB13A/D2/SPID5 (io), 94 PB13B/D1/SPID6 (io), 95 PB14A/BDQS14 (io), 96 PB14B/D3/SPID4 (io), 97 PB15A (io), 98 PB15B/D4/SPID3 (io), 99 PB16A (io), 100 PB16B/D5/SPID2 (io), 101 PB17A (io), 102 PB17B/D6/SPID1 (io)
part F pins: 65 PB2A (io), 66 PB2B (io), 67 PB3A (io), 68 PB3B (io), 69 PB4A (io), 70 PB4B (io), 71 PB5A (io), 73 PB5B (io), 75 PB6A/BDQS6 (io), 76 PB6B (io), 77 PB7A (io), 78 PB7B (io), 79 PB8A/VREF2_5 (io), 80 PB8B/VREF1_5 (io), 81 PB9A/PCLKT5_0 (io), 83 PB9B/PCLKC5_0 (io)
part G pins: 33 PL7A/LLM0_PLLT_IN_A (io), 34 PL7B/LLM0_PLLC_IN_A (io), 35 PL8A/LLM0_PLLT_FB_A (io), 36 PL8B/LLM0_PLLC_FB_A (io), 38 PL9A (io), 39 PL9B (io), 40 PL10A (io), 42 PL10B (io), 43 PL11A/LDQS11 (io), 44 PL11B (io), 45 PL12A (io), 46 PL12B (io), 47 PL13A (io), 48 PL13B (io), 49 PL14A/VREF1_6 (io), 50 PL14B/VREF2_6 (io)
part H pins: 3 PL2A/VREF2_7 (io), 4 PL2B/VREF1_7 (io), 15 PL3A (io), 16 PL3B (io), 17 PL4A (io), 19 PL4B (io), 20 PL5A/PCLKT7_0 (io), 21 PL5B/PCLKC7_0 (io)
part I pins: 23 XRES, 27 TCK (in), 29 TDI (in), 30 TMS (in), 31 TDO (out), 125 CFG2 (in), 126 CFG1 (in), 127 CFG0 (in), 129 PROGRAMN (in), 130 CCLK (io), 131 INITN (io), 133 DONE (io)
part J pins: 2 VCCIO7 (power), 26 VCC (power), 32 VCCJ (power), 37 VCCIO6 (power), 51 VCCIO6 (power), 53 VCCIO5 (power), 74 VCCIO5 (power), 84 VCCAUX (power), 85 VCCIO4 (power), 104 VCCIO4 (power), 106 VCCIO3 (power), 120 VCCIO3 (power), 128 VCC (power), 135 VCC (power), 155 VCCIO2 (power), 157 VCCIO1 (power), 176 VCCIO1 (power), 177 VCCAUX (power), 187 VCCIO0 (power), 208 VCCIO0 (power)
part K pins: 1 GND0-GND7 (power), 28 GND (power), 41 GND6 (power), 52 GND5-GND6 (power), 82 GND5 (power), 93 GND4 (power), 105 GND3-GND4 (power), 116 GND3 (power), 132 GND (power), 134 GND (power), 156 GND1-GND2 (power), 168 GND1 (power), 179 GND0 (power)
part L pins: 5 NC, 6 NC, 7 NC, 8 NC, 9 NC, 10 NC, 11 NC, 12 NC, 13 NC, 14 NC, 18 NC, 22 NC, 24 NC, 25 NC, 54 NC, 55 NC, 56 NC, 57 NC, 58 NC, 59 NC, 60 NC, 61 NC, 62 NC, 63 NC, 64 NC, 72 NC, 103 NC, 136 NC, 138 NC, 144 NC, 145 NC, 146 NC, 147 NC, 148 NC, 149 NC, 150 NC, 151 NC, 152 NC, 158 NC, 189 NC, 197 NC, 198 NC, 199 NC, 200 NC, 201 NC, 202 NC, 203 NC, 204 NC, 205 NC, 206 NC, 207 NC

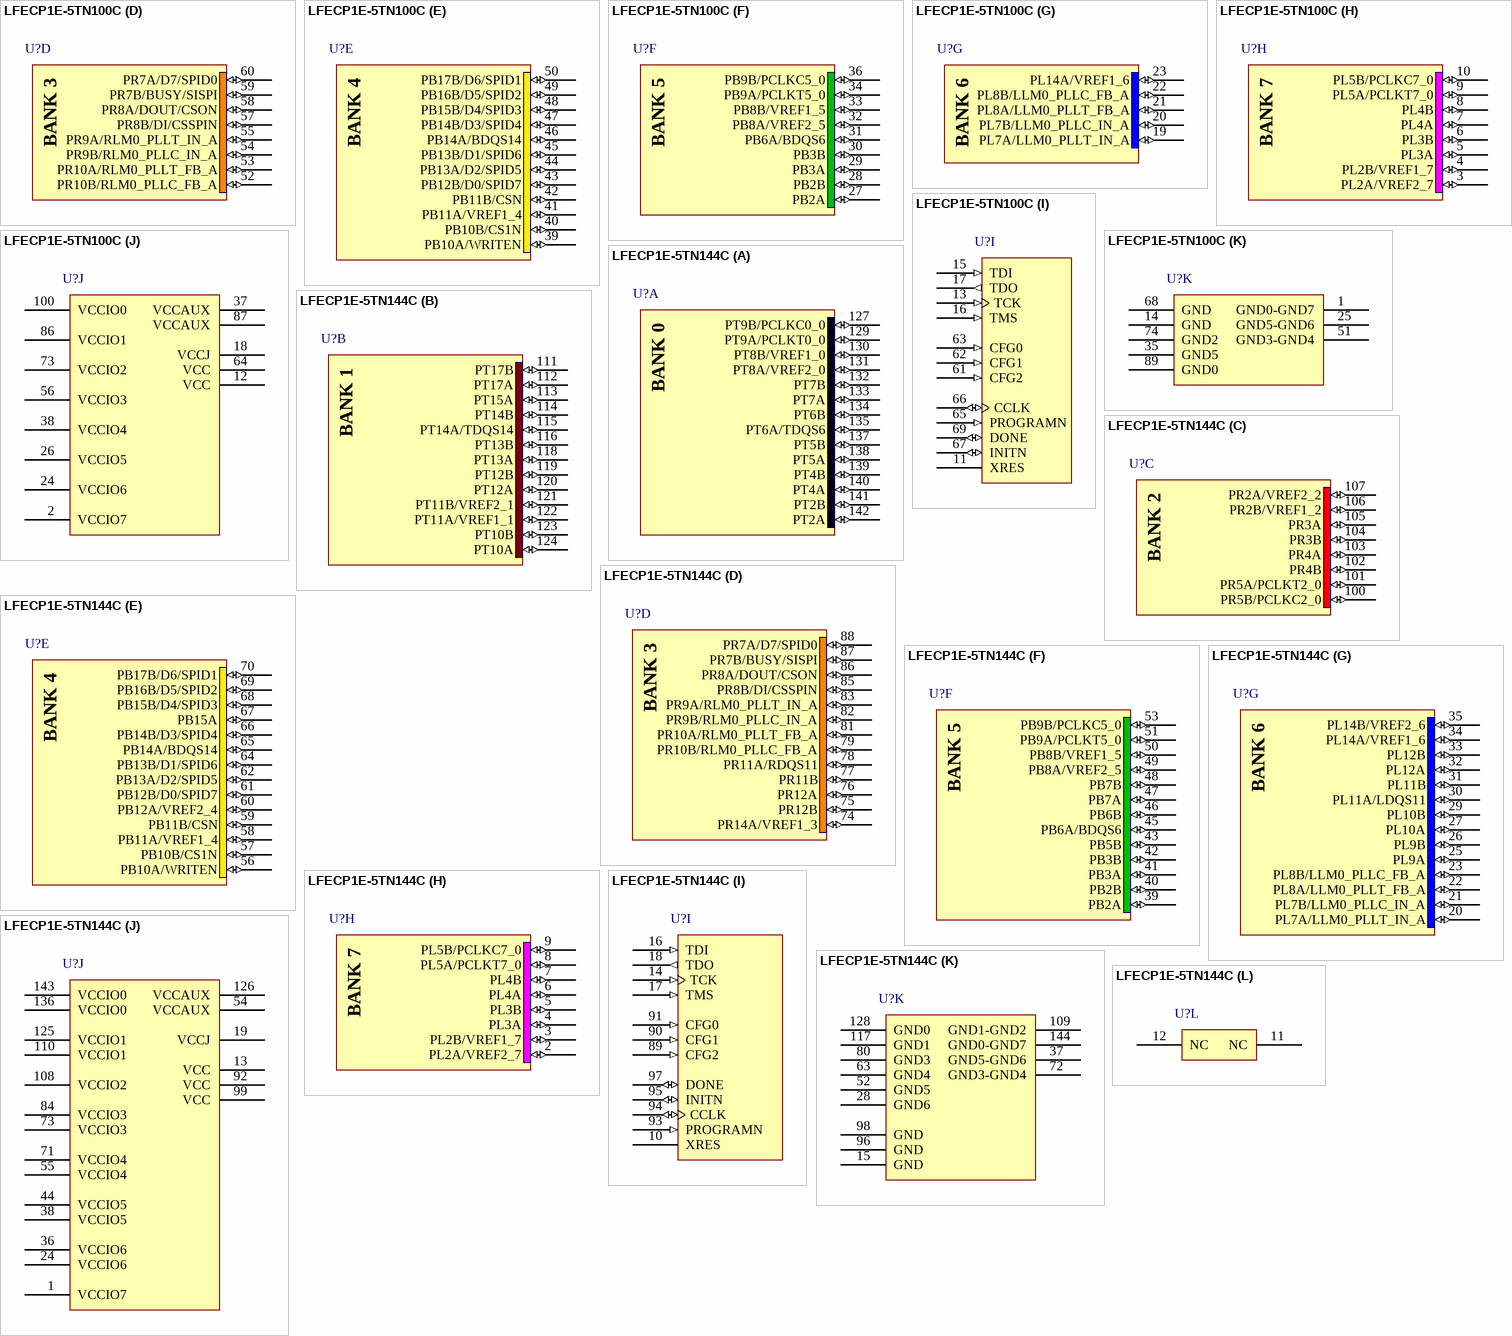
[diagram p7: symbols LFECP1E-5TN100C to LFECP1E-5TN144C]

## LFECP1E-5TN100C
designator U?
ECP 1.2V FPGA, 67 I/Os, 2 PLLs, 1.5K LUTs, 100-Pin TQFP, Pb-Free, Speed Grade 5, Commercial Temperature Grade; Note: Pins 1, 25 and 51 are double bonded.; ComponentAvailability: Not Available
footprint TQFP100_N (Thin QFP, 100-Leads, Body 14x14mm, Pitch 0.5mm, IPC Medium Density)
footprint TQFP100_L (Thin QFP, 100-Leads, Body 14x14mm, Pitch 0.5mm, IPC High Density)
footprint TQFP100_M (Thin QFP, 100-Leads, Body 14x14mm, Pitch 0.5mm, IPC Low Density)
3D model ECP1E-TQFP-100 (100-Pin Thin Quad Flat Pack (TQFP100))
part A pins: 88 PT9B/PCLKC0_0 (io), 90 PT9A/PCLKT0_0 (io), 91 PT8B/VREF1_0 (io), 92 PT8A/VREF2_0 (io), 93 PT7B (io), 94 PT6B (io), 95 PT6A/TDQS6 (io), 96 PT4B (io), 97 PT4A (io), 98 PT2B (io), 99 PT2A (io)
part B pins: 75 PT17B (io), 76 PT17A (io), 77 PT14B (io), 78 PT14A/TDQS14 (io), 79 PT13A (io), 80 PT12B (io), 81 PT12A (io), 82 PT11B/VREF2_1 (io), 83 PT11A/VREF1_1 (io), 84 PT10B (io), 85 PT10A (io)
part C pins: 70 PR5B/PCLKC2_0 (io), 71 PR5A/PCLKT2_0 (io), 72 PR2B/VREF1_2 (io)
part D pins: 52 PR10B/RLM0_PLLC_FB_A (io), 53 PR10A/RLM0_PLLT_FB_A (io), 54 PR9B/RLM0_PLLC_IN_A (io), 55 PR9A/RLM0_PLLT_IN_A (io), 57 PR8B/DI/CSSPIN (io), 58 PR8A/DOUT/CSON (io), 59 PR7B/BUSY/SISPI (io), 60 PR7A/D7/SPID0 (io)
part E pins: 39 PB10A/WRITEN (io), 40 PB10B/CS1N (io), 41 PB11A/VREF1_4 (io), 42 PB11B/CSN (io), 43 PB12B/D0/SPID7 (io), 44 PB13A/D2/SPID5 (io), 45 PB13B/D1/SPID6 (io), 46 PB14A/BDQS14 (io), 47 PB14B/D3/SPID4 (io), 48 PB15B/D4/SPID3 (io), 49 PB16B/D5/SPID2 (io), 50 PB17B/D6/SPID1 (io)
part F pins: 27 PB2A (io), 28 PB2B (io), 29 PB3A (io), 30 PB3B (io), 31 PB6A/BDQS6 (io), 32 PB8A/VREF2_5 (io), 33 PB8B/VREF1_5 (io), 34 PB9A/PCLKT5_0 (io), 36 PB9B/PCLKC5_0 (io)
part G pins: 19 PL7A/LLM0_PLLT_IN_A (io), 20 PL7B/LLM0_PLLC_IN_A (io), 21 PL8A/LLM0_PLLT_FB_A (io), 22 PL8B/LLM0_PLLC_FB_A (io), 23 PL14A/VREF1_6 (io)
part H pins: 3 PL2A/VREF2_7 (io), 4 PL2B/VREF1_7 (io), 5 PL3A (io), 6 PL3B (io), 7 PL4A (io), 8 PL4B (io), 9 PL5A/PCLKT7_0 (io), 10 PL5B/PCLKC7_0 (io)
part I pins: 11 XRES, 13 TCK (in), 15 TDI (in), 16 TMS (in), 17 TDO (out), 61 CFG2 (in), 62 CFG1 (in), 63 CFG0 (in), 65 PROGRAMN (in), 66 CCLK (io), 67 INITN (io), 69 DONE (io)
part J pins: 2 VCCIO7 (power), 12 VCC (power), 18 VCCJ (power), 24 VCCIO6 (power), 26 VCCIO5 (power), 37 VCCAUX (power), 38 VCCIO4 (power), 56 VCCIO3 (power), 64 VCC (power), 73 VCCIO2 (power), 86 VCCIO1 (power), 87 VCCAUX (power), 100 VCCIO0 (power)
part K pins: 1 GND0-GND7 (power), 14 GND (power), 25 GND5-GND6 (power), 35 GND5 (power), 51 GND3-GND4 (power), 68 GND (power), 74 GND2 (power), 89 GND0 (power)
